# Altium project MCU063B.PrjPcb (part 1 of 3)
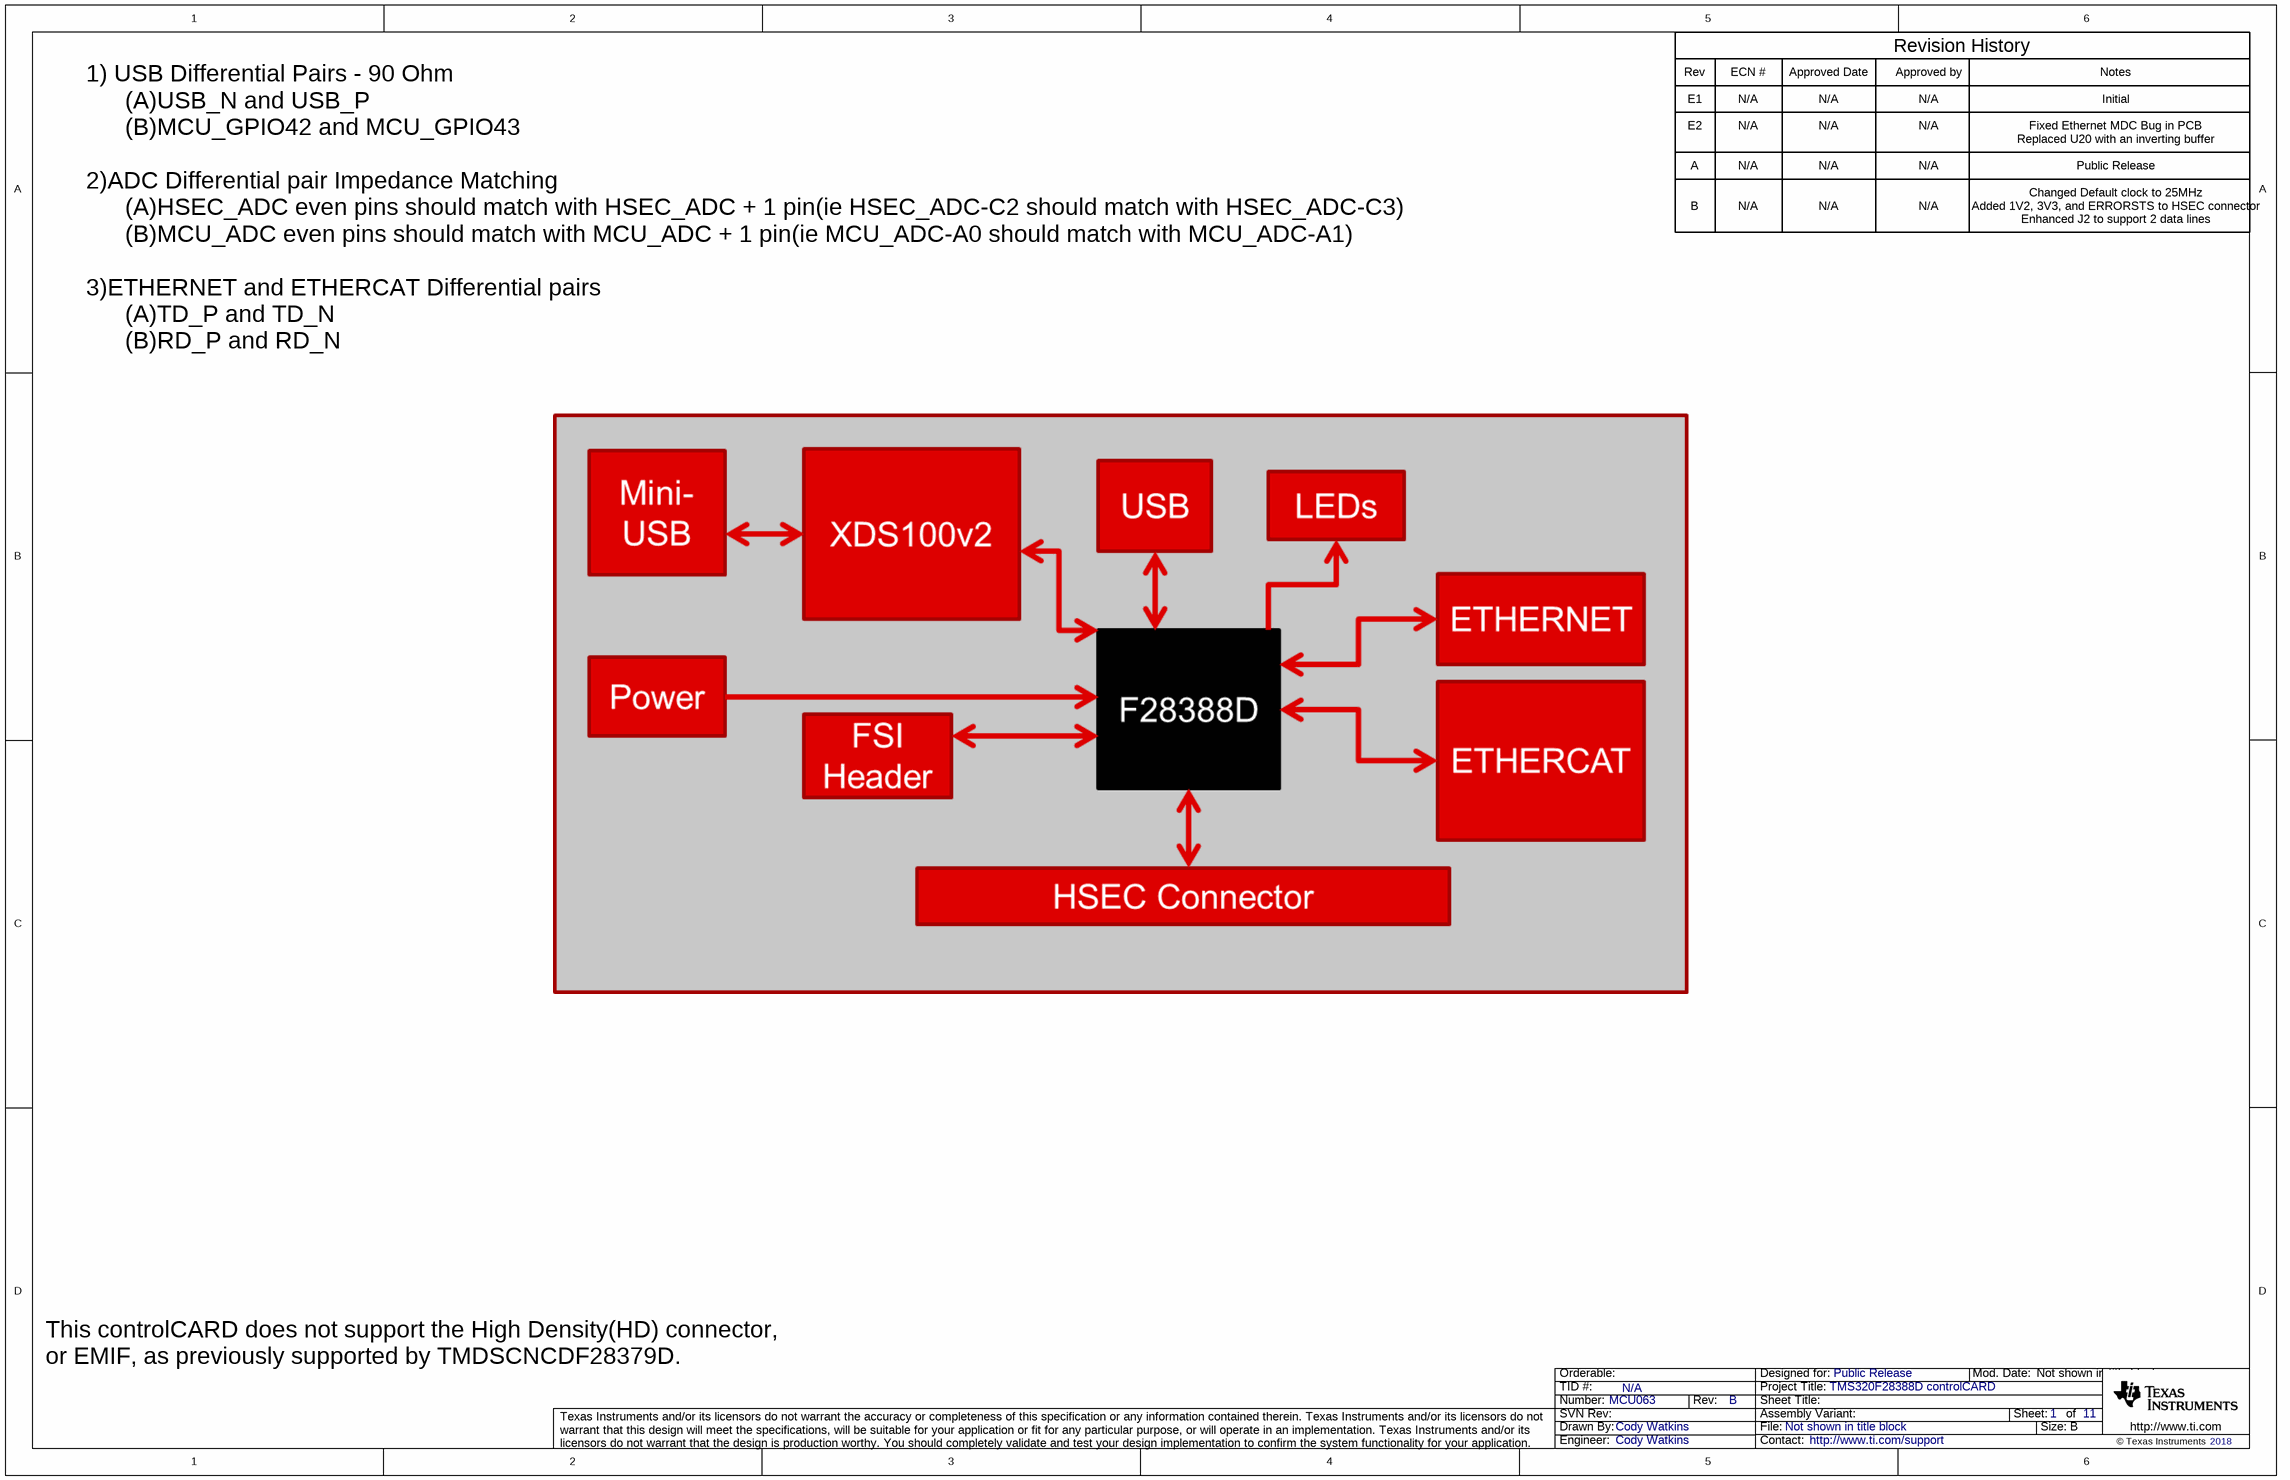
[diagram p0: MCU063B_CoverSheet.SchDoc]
CopyrightYear: 2018; PCB_Layout: QCG; PCB_Rev: B; PRJ_Customer: Public Release; PRJ_Engineer: Cody Watkins; PRJ_Number: MCU063; PRJ_Title: TMS320F28388D controlCARD; SCH_Rev: B; TechSupport: http://www.ti.com/support; TID: N/A
11 sheets, 441 parts. Net scope: global (net labels, ports and power ports of the same name join across sheets).
Board file: MCU063B_PCB.PcbDoc
Sheets:
  MCU063B_CoverSheet.SchDoc
  MCU063B_GPIO.SchDoc
  MCU063B_Support.SchDoc
  MCU063B_ADC.SchDoc
  MCU063B_Power.SchDoc
  MCU063B_USB.SchDoc
  MCU063B_EtherNET.SchDoc
  MCU063B_EtherCAT.SchDoc
  MCU063B_Emulator.SchDoc
  MCU063B_Emulator_interface.SchDoc
  MCU063B_EVM_Hardware.SchDoc

## Sheet MCU063B_CoverSheet.SchDoc
size 431 x 279 mm; Date: Not shown in title block; ApprovedBy: Not shown in title block; CheckedBy: Not shown in title block; Author: Not shown in title block; CompanyName: Not shown in title block; DrawnBy: Cody Watkins; Engineer: Not shown in title block; Organization: Not shown in title block; Address1: Not shown in title block; Address2: Not shown in title block; Address3: Not shown in title block; Address4: Not shown in title block; DocumentNumber: 1; Revision: Use project parameter SCH_Rev; SheetNumber: 1; SheetTotal: 11; PageSetup: Record=PageOptions¦CenterHorizontal=True¦CenterVertical=True¦PrintScale=1.00¦XCorrection=1.00¦YCorrection=1.00¦PrintKind=0¦BorderSize=5000000¦LeftOffset=0¦BottomOffset=0¦Orientation=2¦PaperLength=1000¦PaperWidth=1000¦Scale=100¦PaperSource=15¦PrintQuality=600¦MediaType=1¦DitherType=10¦PaperKind=Letter¦PrintScaleMode=1

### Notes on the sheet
- Rev
- E1
- ECN #
- N/A
- Approved Date
- Approved by
- Revision History
- Notes
- Initial
- E2
- A
- Public Release
- Fixed Ethernet MDC Bug in PCB
- Replaced U20 with an inverting buffer
- B
- Changed Default clock to 25MHz
- Added 1V2, 3V3, and ERRORSTS to HSEC connector
- Enhanced J2 to support 2 data lines
- 1) USB Differential Pairs - 90 Ohm
  (A)USB_N and USB_P
  (B)MCU_GPIO42 and MCU_GPIO43
  2)ADC Differential pair Impedance Matching
  (A)HSEC_ADC even pins should match with HSEC_ADC + 1 pin(ie HSEC_ADC-C2 should match with HSEC_ADC-C3)
  (B)MCU_ADC even pins should match with MCU_ADC + 1 pin(ie MCU_ADC-A0 should match with MCU_ADC-A1)
  3)ETHERNET and ETHERCAT Differential pairs
  (A)TD_P and TD_N
  (B)RD_P and RD_N
- This controlCARD does not support the High Density(HD) connector, or EMIF, as previously supported by TMDSCNCDF28379D.

## Sheet MCU063B_GPIO.SchDoc
size 431 x 279 mm; Date: Not shown in title block; ApprovedBy: Not shown in title block; CheckedBy: Not shown in title block; Author: Not shown in title block; CompanyName: Not shown in title block; DrawnBy: Cody Watkins; Engineer: Not shown in title block; Organization: Not shown in title block; Address1: Not shown in title block; Address2: Not shown in title block; Address3: Not shown in title block; Address4: Not shown in title block; DocumentNumber: 2; Revision: Use project parameter SCH_Rev; SheetNumber: 2; SheetTotal: 11; PageSetup: Record=PageOptions¦CenterHorizontal=True¦CenterVertical=True¦PrintScale=1.00¦XCorrection=1.00¦YCorrection=1.00¦PrintKind=0¦BorderSize=5000000¦LeftOffset=0¦BottomOffset=0¦Orientation=2¦PaperLength=1000¦PaperWidth=1000¦Scale=100¦PaperSource=15¦PrintQuality=600¦MediaType=1¦DitherType=10¦PaperKind=Letter¦PrintScaleMode=1
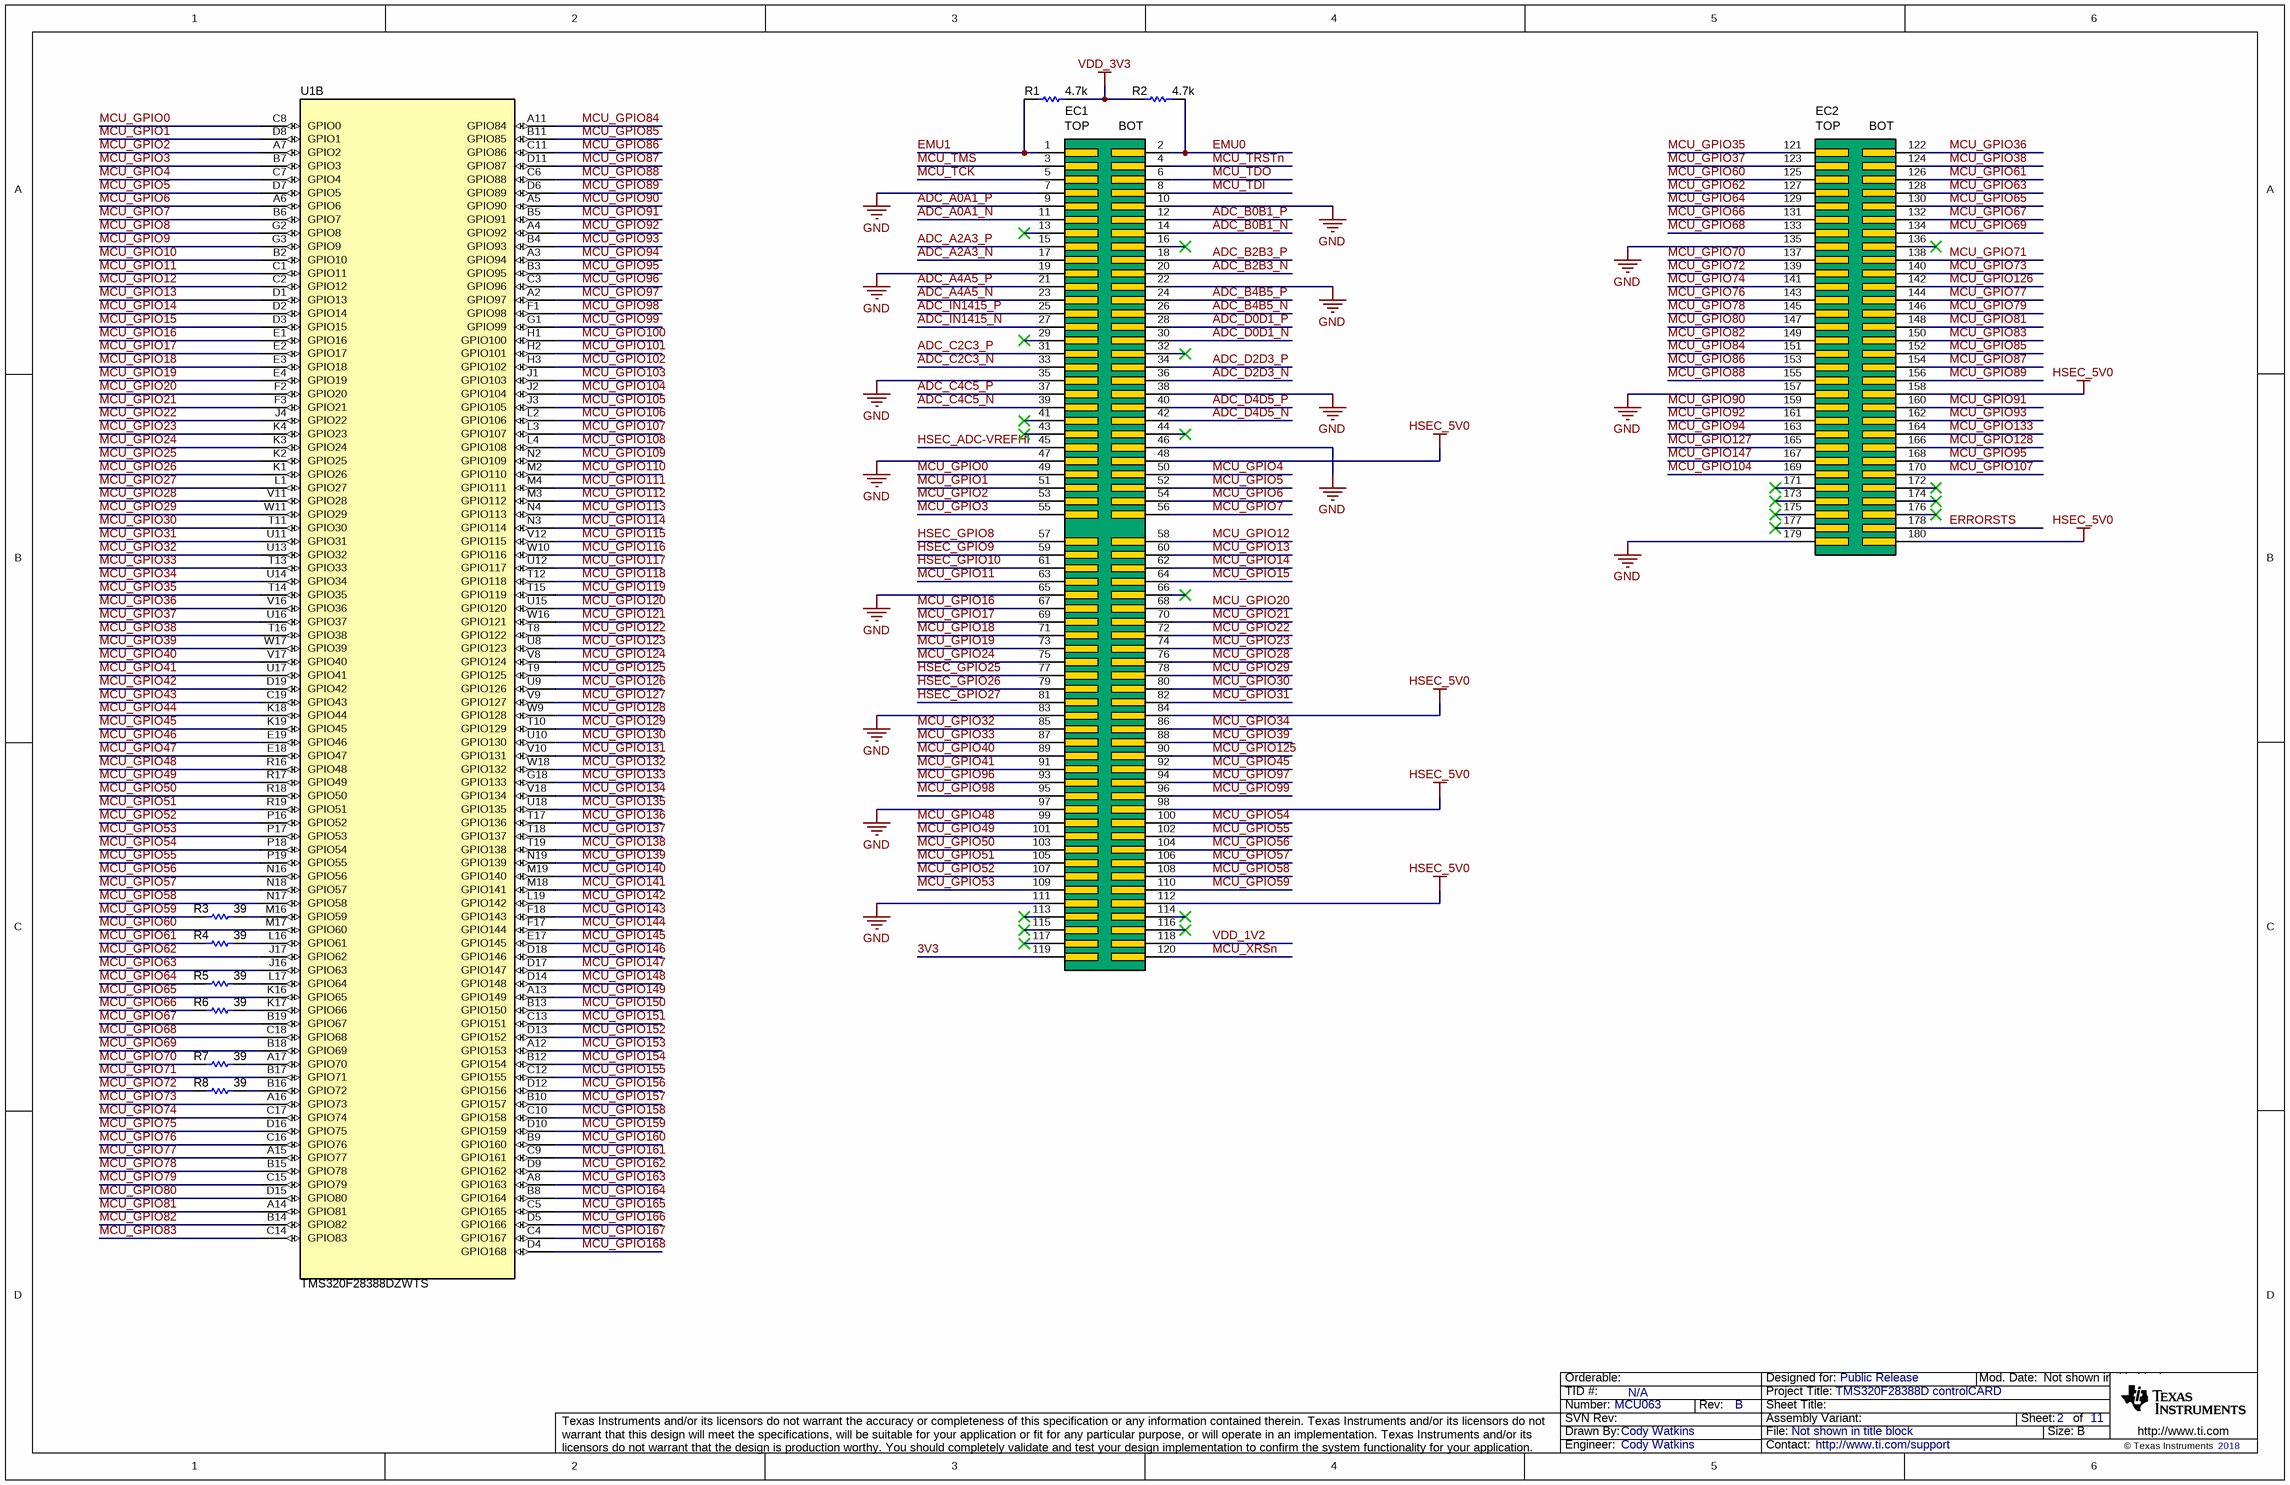
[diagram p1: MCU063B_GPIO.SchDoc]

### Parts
EC1  controlCARD-120HSEC_Edge  [controlCARD-120HSEC_Edge]  (value not drawn)  (no BOM)
EC2  controlCARD-180HSEC-60pinAddon_Edge  [controlCARD-180HSEC-60pinAddon_Edge]  (value not drawn)  (no BOM)
R1  ValueDisplayed: 4.7k  [0402]  (hidden comment: CRCW04024K70JNED)
R2  ValueDisplayed: 4.7k  [0402]  (hidden comment: CRCW04024K70JNED)
R3  ValueDisplayed: 39  [0402]  (hidden comment: CRCW040239R0JNED)
R4  ValueDisplayed: 39  [0402]  (hidden comment: CRCW040239R0JNED)
R5  ValueDisplayed: 39  [0402]  (hidden comment: CRCW040239R0JNED)
R6  ValueDisplayed: 39  [0402]  (hidden comment: CRCW040239R0JNED)
R7  ValueDisplayed: 39  [0402]  (hidden comment: CRCW040239R0JNED)
R8  ValueDisplayed: 39  [0402]  (hidden comment: CRCW040239R0JNED)
U1  TMS320F28388DZWTS  [ZWT0337A]  (part B of 5)

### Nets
3V3: EC1.119
GND: EC1.7 EC1.10 EC1.19 EC1.22 EC1.35 EC1.38 EC1.46 EC1.47 EC1.65 EC1.83 EC1.97 EC1.111 EC2.135 EC2.157 EC2.179
HSEC_5V0: EC1.48 EC1.84 EC1.98 EC1.112 EC2.158 EC2.180
VDD_1V2: EC1.118
VDD_3V3: R1.2 R2.1
ADC_A0A1_N: EC1.11
ADC_A0A1_P: EC1.9
ADC_A2A3_N: EC1.17
ADC_A2A3_P: EC1.15
ADC_A4A5_N: EC1.23
ADC_A4A5_P: EC1.21
ADC_B0B1_N: EC1.14
ADC_B0B1_P: EC1.12
ADC_B2B3_N: EC1.20
ADC_B2B3_P: EC1.18
ADC_B4B5_N: EC1.26
ADC_B4B5_P: EC1.24
ADC_C2C3_N: EC1.33
ADC_C2C3_P: EC1.31
ADC_C4C5_N: EC1.39
ADC_C4C5_P: EC1.37
ADC_D0D1_N: EC1.30
ADC_D0D1_P: EC1.28
ADC_D2D3_N: EC1.36
ADC_D2D3_P: EC1.34
ADC_D4D5_N: EC1.42
ADC_D4D5_P: EC1.40
ADC_IN1415_N: EC1.27
ADC_IN1415_P: EC1.25
EMU0: EC1.2 R2.2
EMU1: EC1.1 R1.1
ERRORSTS: EC2.178
HSEC_ADC-VREFHI: EC1.45
HSEC_GPIO8: EC1.57
HSEC_GPIO9: EC1.59
HSEC_GPIO10: EC1.61
HSEC_GPIO25: EC1.77
HSEC_GPIO26: EC1.79
HSEC_GPIO27: EC1.81
MCU_GPIO0: EC1.49 U1.C8(GPIO0)
MCU_GPIO1: EC1.51 U1.D8(GPIO1)
MCU_GPIO2: EC1.53 U1.A7(GPIO2)
MCU_GPIO3: EC1.55 U1.B7(GPIO3)
MCU_GPIO4: EC1.50 U1.C7(GPIO4)
MCU_GPIO5: EC1.52 U1.D7(GPIO5)
MCU_GPIO6: EC1.54 U1.A6(GPIO6)
MCU_GPIO7: EC1.56 U1.B6(GPIO7)
MCU_GPIO8: U1.G2(GPIO8)
MCU_GPIO9: U1.G3(GPIO9)
MCU_GPIO10: U1.B2(GPIO10)
MCU_GPIO11: EC1.63 U1.C1(GPIO11)
MCU_GPIO12: EC1.58 U1.C2(GPIO12)
MCU_GPIO13: EC1.60 U1.D1(GPIO13)
MCU_GPIO14: EC1.62 U1.D2(GPIO14)
MCU_GPIO15: EC1.64 U1.D3(GPIO15)
MCU_GPIO16: EC1.67 U1.E1(GPIO16)
MCU_GPIO17: EC1.69 U1.E2(GPIO17)
MCU_GPIO18: EC1.71 U1.E3(GPIO18)
MCU_GPIO19: EC1.73 U1.E4(GPIO19)
MCU_GPIO20: EC1.68 U1.F2(GPIO20)
MCU_GPIO21: EC1.70 U1.F3(GPIO21)
MCU_GPIO22: EC1.72 U1.J4(GPIO22)
MCU_GPIO23: EC1.74 U1.K4(GPIO23)
MCU_GPIO24: EC1.75 U1.K3(GPIO24)
MCU_GPIO25: U1.K2(GPIO25)
MCU_GPIO26: U1.K1(GPIO26)
MCU_GPIO27: U1.L1(GPIO27)
MCU_GPIO28: EC1.76 U1.V11(GPIO28)
MCU_GPIO29: EC1.78 U1.W11(GPIO29)
MCU_GPIO30: EC1.80 U1.T11(GPIO30)
MCU_GPIO31: EC1.82 U1.U11(GPIO31)
MCU_GPIO32: EC1.85 U1.U13(GPIO32)
MCU_GPIO33: EC1.87 U1.T13(GPIO33)
MCU_GPIO34: EC1.86 U1.U14(GPIO34)
MCU_GPIO35: EC2.121 U1.T14(GPIO35)
MCU_GPIO36: EC2.122 U1.V16(GPIO36)
MCU_GPIO37: EC2.123 U1.U16(GPIO37)
MCU_GPIO38: EC2.124 U1.T16(GPIO38)
MCU_GPIO39: EC1.88 U1.W17(GPIO39)
MCU_GPIO40: EC1.89 U1.V17(GPIO40)
MCU_GPIO41: EC1.91 U1.U17(GPIO41)
MCU_GPIO42: U1.D19(GPIO42)
MCU_GPIO43: U1.C19(GPIO43)
MCU_GPIO44: U1.K18(GPIO44)
MCU_GPIO45: EC1.92 U1.K19(GPIO45)
MCU_GPIO46: U1.E19(GPIO46)
MCU_GPIO47: U1.E18(GPIO47)
MCU_GPIO48: EC1.99 U1.R16(GPIO48)
MCU_GPIO49: EC1.101 U1.R17(GPIO49)
MCU_GPIO50: EC1.103 U1.R18(GPIO50)
MCU_GPIO51: EC1.105 U1.R19(GPIO51)
MCU_GPIO52: EC1.107 U1.P16(GPIO52)
MCU_GPIO53: EC1.109 U1.P17(GPIO53)
MCU_GPIO54: EC1.100 U1.P18(GPIO54)
MCU_GPIO55: EC1.102 U1.P19(GPIO55)
MCU_GPIO56: EC1.104 U1.N16(GPIO56)
MCU_GPIO57: EC1.106 U1.N18(GPIO57)
MCU_GPIO58: EC1.108 U1.N17(GPIO58)
MCU_GPIO59: EC1.110 R3.1
MCU_GPIO60: EC2.125 U1.M17(GPIO60)
MCU_GPIO61: EC2.126 R4.1
MCU_GPIO62: EC2.127 U1.J17(GPIO62)
MCU_GPIO63: EC2.128 U1.J16(GPIO63)
MCU_GPIO64: EC2.129 R5.1
MCU_GPIO65: EC2.130 U1.K16(GPIO65)
MCU_GPIO66: EC2.131 R6.1
MCU_GPIO67: EC2.132 U1.B19(GPIO67)
MCU_GPIO68: EC2.133 U1.C18(GPIO68)
MCU_GPIO69: EC2.134 U1.B18(GPIO69)
MCU_GPIO70: EC2.137 R7.1
MCU_GPIO71: EC2.138 U1.B17(GPIO71)
MCU_GPIO72: EC2.139 R8.1
MCU_GPIO73: EC2.140 U1.A16(GPIO73)
MCU_GPIO74: EC2.141 U1.C17(GPIO74)
MCU_GPIO75: U1.D16(GPIO75)
MCU_GPIO76: EC2.143 U1.C16(GPIO76)
MCU_GPIO77: EC2.144 U1.A15(GPIO77)
MCU_GPIO78: EC2.145 U1.B15(GPIO78)
MCU_GPIO79: EC2.146 U1.C15(GPIO79)
MCU_GPIO80: EC2.147 U1.D15(GPIO80)
MCU_GPIO81: EC2.148 U1.A14(GPIO81)
MCU_GPIO82: EC2.149 U1.B14(GPIO82)
MCU_GPIO83: EC2.150 U1.C14(GPIO83)
MCU_GPIO84: EC2.151 U1.A11(GPIO84)
MCU_GPIO85: EC2.152 U1.B11(GPIO85)
MCU_GPIO86: EC2.153 U1.C11(GPIO86)
MCU_GPIO87: EC2.154 U1.D11(GPIO87)
MCU_GPIO88: EC2.155 U1.C6(GPIO88)
MCU_GPIO89: EC2.156 U1.D6(GPIO89)
MCU_GPIO90: EC2.159 U1.A5(GPIO90)
MCU_GPIO91: EC2.160 U1.B5(GPIO91)
MCU_GPIO92: EC2.161 U1.A4(GPIO92)
MCU_GPIO93: EC2.162 U1.B4(GPIO93)
MCU_GPIO94: EC2.163 U1.A3(GPIO94)
MCU_GPIO95: EC2.168 U1.B3(GPIO95)
MCU_GPIO96: EC1.93 U1.C3(GPIO96)
MCU_GPIO97: EC1.94 U1.A2(GPIO97)
MCU_GPIO98: EC1.95 U1.F1(GPIO98)
MCU_GPIO99: EC1.96 U1.G1(GPIO99)
MCU_GPIO100: U1.H1(GPIO100)
MCU_GPIO101: U1.H2(GPIO101)
MCU_GPIO102: U1.H3(GPIO102)
MCU_GPIO103: U1.J1(GPIO103)
MCU_GPIO104: EC2.169 U1.J2(GPIO104)
MCU_GPIO105: U1.J3(GPIO105)
MCU_GPIO106: U1.L2(GPIO106)
MCU_GPIO107: EC2.170 U1.L3(GPIO107)
MCU_GPIO108: U1.L4(GPIO108)
MCU_GPIO109: U1.N2(GPIO109)
MCU_GPIO110: U1.M2(GPIO110)
MCU_GPIO111: U1.M4(GPIO111)
MCU_GPIO112: U1.M3(GPIO112)
MCU_GPIO113: U1.N4(GPIO113)
MCU_GPIO114: U1.N3(GPIO114)
MCU_GPIO115: U1.V12(GPIO115)
MCU_GPIO116: U1.W10(GPIO116)
MCU_GPIO117: U1.U12(GPIO117)
MCU_GPIO118: U1.T12(GPIO118)
MCU_GPIO119: U1.T15(GPIO119)
MCU_GPIO120: U1.U15(GPIO120)
MCU_GPIO121: U1.W16(GPIO121)
MCU_GPIO122: U1.T8(GPIO122)
MCU_GPIO123: U1.U8(GPIO123)
MCU_GPIO124: U1.V8(GPIO124)
MCU_GPIO125: EC1.90 U1.T9(GPIO125)
MCU_GPIO126: EC2.142 U1.U9(GPIO126)
MCU_GPIO127: EC2.165 U1.V9(GPIO127)
MCU_GPIO128: EC2.166 U1.W9(GPIO128)
MCU_GPIO129: U1.T10(GPIO129)
MCU_GPIO130: U1.U10(GPIO130)
MCU_GPIO131: U1.V10(GPIO131)
MCU_GPIO132: U1.W18(GPIO132)
MCU_GPIO133: EC2.164 U1.G18(GPIO133)
MCU_GPIO134: U1.V18(GPIO134)
MCU_GPIO135: U1.U18(GPIO135)
MCU_GPIO136: U1.T17(GPIO136)
MCU_GPIO137: U1.T18(GPIO137)
MCU_GPIO138: U1.T19(GPIO138)
MCU_GPIO139: U1.N19(GPIO139)
MCU_GPIO140: U1.M19(GPIO140)
MCU_GPIO141: U1.M18(GPIO141)
MCU_GPIO142: U1.L19(GPIO142)
MCU_GPIO143: U1.F18(GPIO143)
MCU_GPIO144: U1.F17(GPIO144)
MCU_GPIO145: U1.E17(GPIO145)
MCU_GPIO146: U1.D18(GPIO146)
MCU_GPIO147: EC2.167 U1.D17(GPIO147)
MCU_GPIO148: U1.D14(GPIO148)
MCU_GPIO149: U1.A13(GPIO149)
MCU_GPIO150: U1.B13(GPIO150)
MCU_GPIO151: U1.C13(GPIO151)
MCU_GPIO152: U1.D13(GPIO152)
MCU_GPIO153: U1.A12(GPIO153)
MCU_GPIO154: U1.B12(GPIO154)
MCU_GPIO155: U1.C12(GPIO155)
MCU_GPIO156: U1.D12(GPIO156)
MCU_GPIO157: U1.B10(GPIO157)
MCU_GPIO158: U1.C10(GPIO158)
MCU_GPIO159: U1.D10(GPIO159)
MCU_GPIO160: U1.B9(GPIO160)
MCU_GPIO161: U1.C9(GPIO161)
MCU_GPIO162: U1.D9(GPIO162)
MCU_GPIO163: U1.A8(GPIO163)
MCU_GPIO164: U1.B8(GPIO164)
MCU_GPIO165: U1.C5(GPIO165)
MCU_GPIO166: U1.D5(GPIO166)
MCU_GPIO167: U1.C4(GPIO167)
MCU_GPIO168: U1.D4(GPIO168)
MCU_TCK: EC1.5
MCU_TDI: EC1.8
MCU_TDO: EC1.6
MCU_TMS: EC1.3
MCU_TRSTn: EC1.4
MCU_XRSn: EC1.120
NetR3_2: R3.2 U1.M16(GPIO59)
NetR4_2: R4.2 U1.L16(GPIO61)
NetR5_2: R5.2 U1.L17(GPIO64)
NetR6_2: R6.2 U1.K17(GPIO66)
NetR7_2: R7.2 U1.A17(GPIO70)
NetR8_2: R8.2 U1.B16(GPIO72)

Not connected (* = marked no-connect by the designer): EC1 13* 16* 29* 32* 41* 43* 44* 66* 113* 114* 115* 116* 117*; EC2 136* 171* 172* 173* 174* 175* 176* 177*

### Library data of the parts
EC1 = CMP-0003813-2: C2000 controlCARD-120HSEC Edge Connector for Samtec HSEC8-160-01-L-DV-A-BL; Manufacturer: Any; Note: The pin numbering does not match Samtec datasheet
EC2 = CMP-0081961-1: C2000 controlCARD-180HSEC (60-pin addon) Edge connector for Samtec HSEC8-130-01-L-DV-A; Manufacturer: Any; Note: The pin numbering does not match Samtec datasheet
R1 R2 = CMP-0026938-5: RES, 4.7 k, 5%, 0.063 W, AEC-Q200 Grade 0, 0402; Manufacturer: Vishay-Dale; Power_W: 63mW; TempCo: 200 ppm/C; Value_Code: 4k70; Value: 4.7k; EIA_Code: E24; SizeX_mm: 1; SizeY_mm: 0.5; SizeZ_mm: 0.6; Value2: 0.063W; AEC Qualified: Y; VDC_V: 50V; AEC Category: Q200; AEC Grade: 0
R3-R8 = CMP-0026916-3: RES, 39, 5%, 0.063 W, AEC-Q200 Grade 0, 0402; Manufacturer: Vishay-Dale; Power_W: 63mW; TempCo: 200 ppm/C; Value_Code: 39R0; Value: 39; EIA_Code: E24; SizeX_mm: 1; SizeY_mm: 0.5; SizeZ_mm: 0.6; Value2: 0.063W; AEC Qualified: Y; VDC_V: 50V; AEC Category: Q200; AEC Grade: 0
U1 = CMP-0081777-3: TMS320F28388DZWTS, ZWT0337A (NFBGA-337); Manufacturer: Texas Instruments; SizeAreaWB_mm2: 324; SizeArea_mm2: 256; AEC Qualified: N; AEC Category: Q200; SizeZ_mm: 1.4; SizeY_mm: 16; CompType: IC

## Sheet MCU063B_Support.SchDoc
size 431 x 279 mm; Date: Not shown in title block; ApprovedBy: Not shown in title block; CheckedBy: Not shown in title block; Author: Not shown in title block; CompanyName: Not shown in title block; DrawnBy: Cody Watkins; Engineer: Not shown in title block; Organization: Not shown in title block; Address1: Not shown in title block; Address2: Not shown in title block; Address3: Not shown in title block; Address4: Not shown in title block; DocumentNumber: 3; Revision: Use project parameter SCH_Rev; SheetNumber: 3; SheetTotal: 11; PageSetup: Record=PageOptions¦CenterHorizontal=True¦CenterVertical=True¦PrintScale=1.00¦XCorrection=1.00¦YCorrection=1.00¦PrintKind=0¦BorderSize=5000000¦LeftOffset=0¦BottomOffset=0¦Orientation=2¦PaperLength=1000¦PaperWidth=1000¦Scale=100¦PaperSource=15¦PrintQuality=600¦MediaType=1¦DitherType=10¦PaperKind=Letter¦PrintScaleMode=1
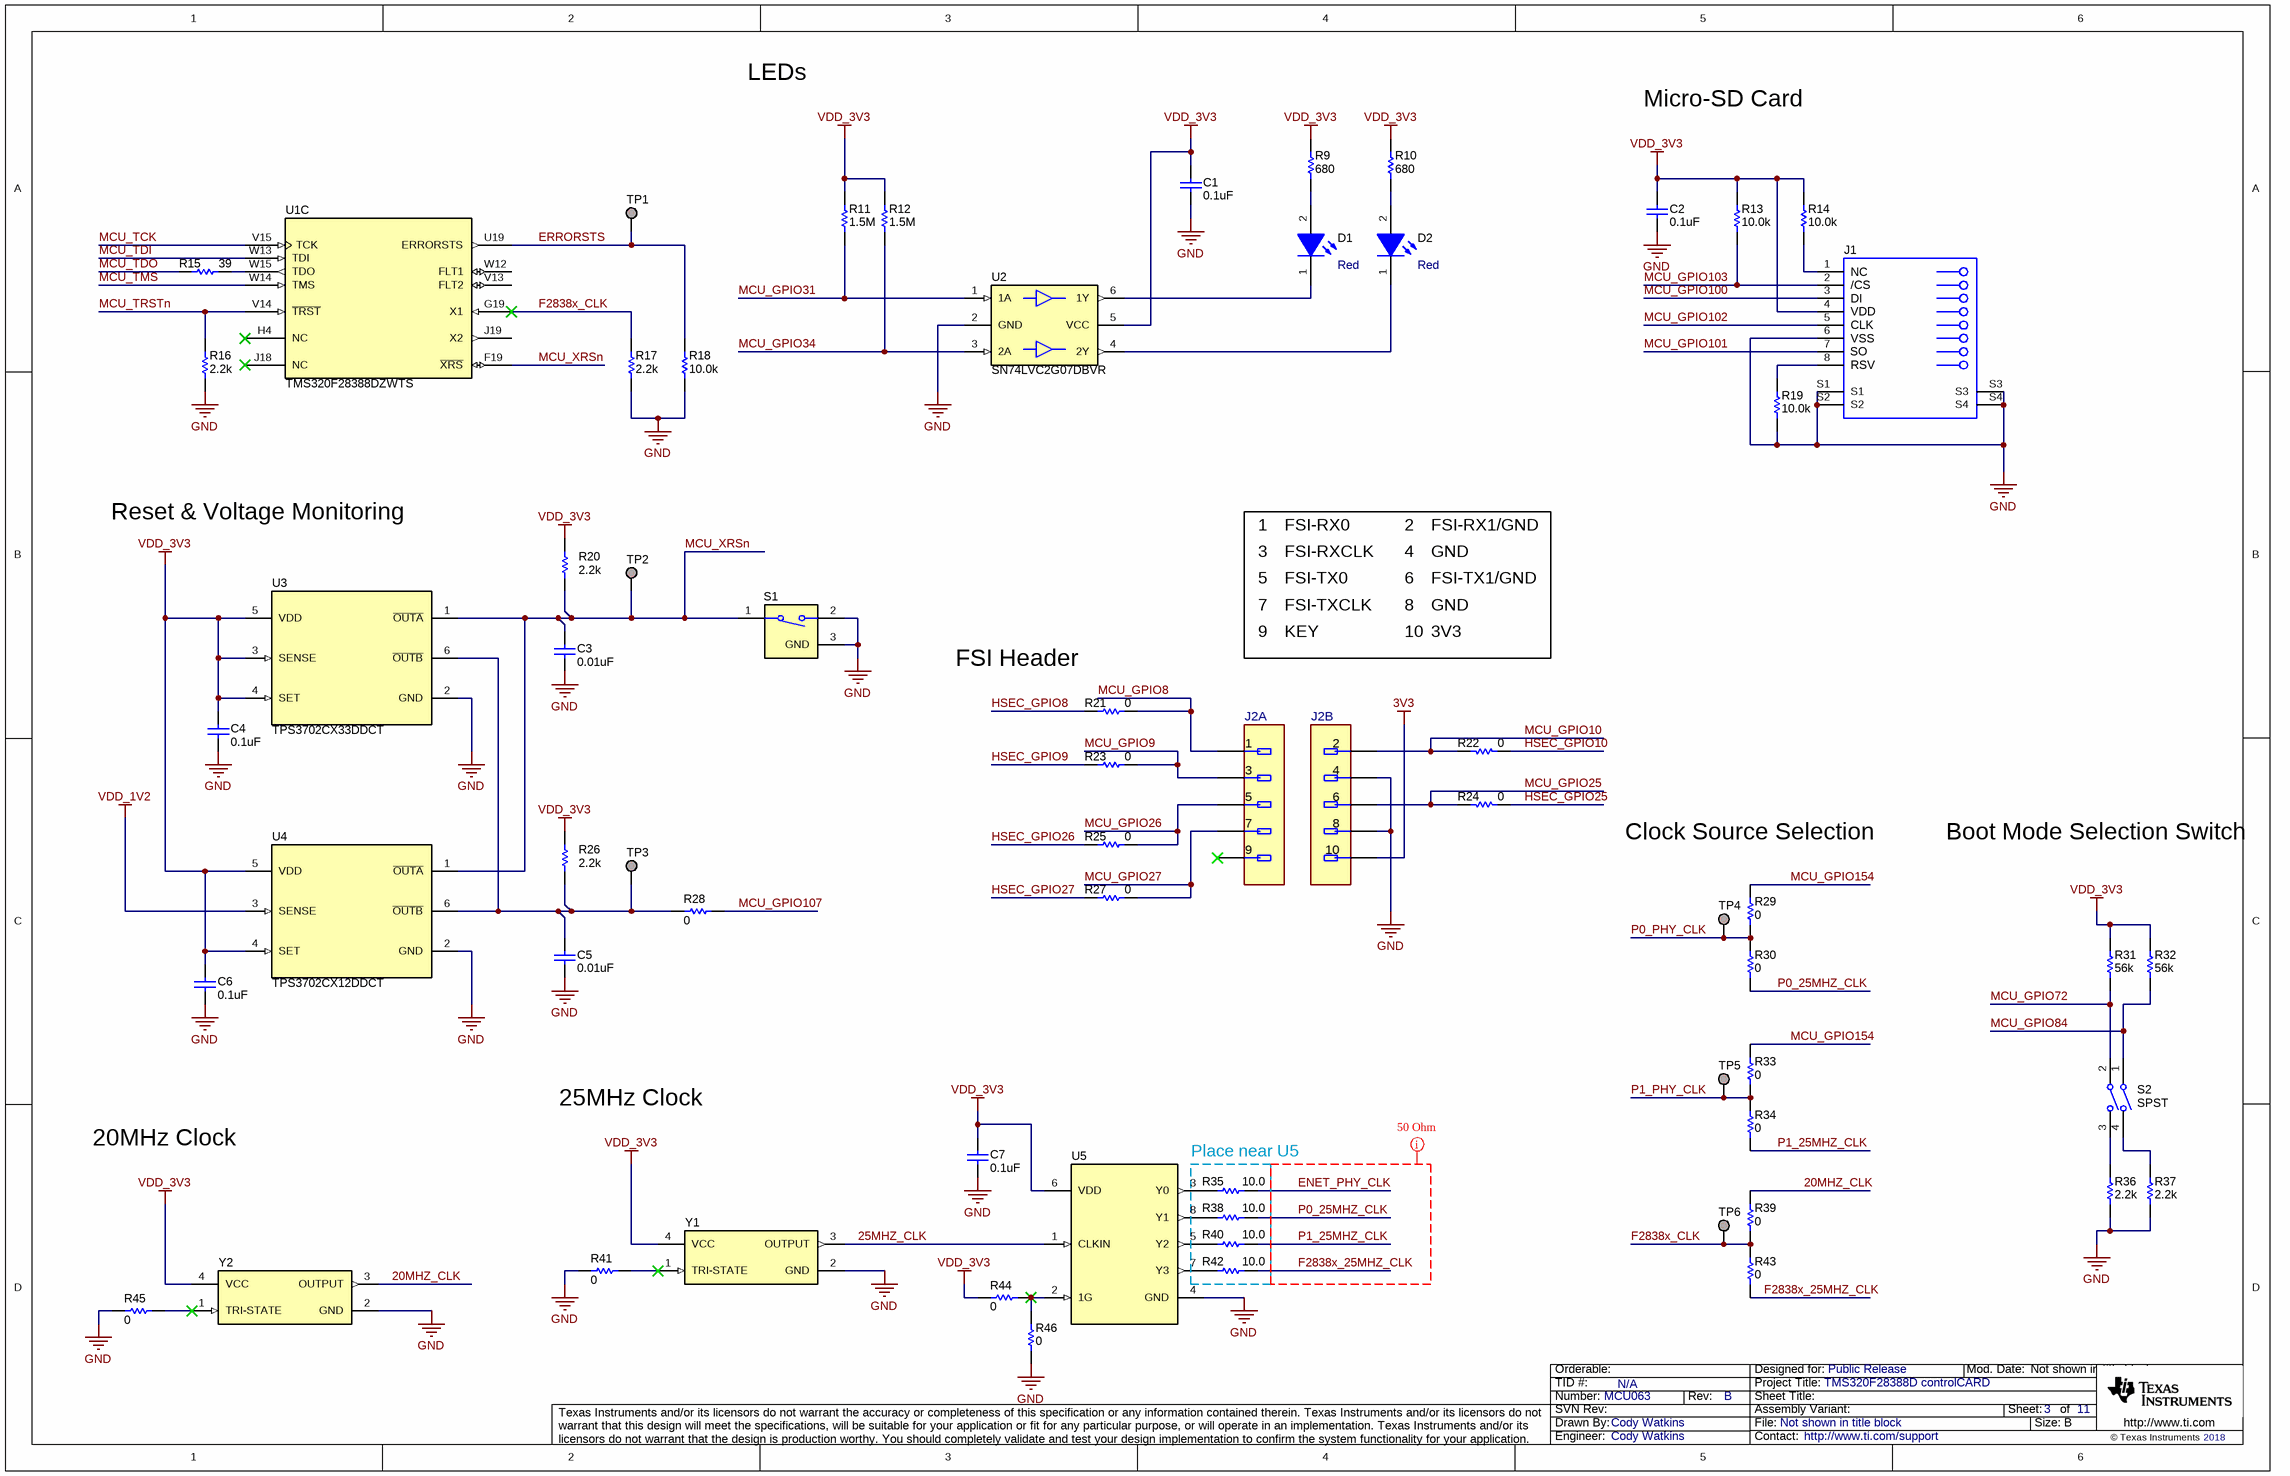
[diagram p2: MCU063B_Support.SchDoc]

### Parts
C1  ValueDisplayed: 0.1uF  [0402]  (hidden comment: CL05B104KP5NNNC)
C2  ValueDisplayed: 0.1uF  [0402]  (hidden comment: CL05B104KP5NNNC)
C3  ValueDisplayed: 0.01uF  [0402]  (hidden comment: C0402C103J5RACTU)
C4  ValueDisplayed: 0.1uF  [0402]  (hidden comment: CL05B104KP5NNNC)
C5  ValueDisplayed: 0.01uF  [0402]  (hidden comment: C0402C103J5RACTU)
C6  ValueDisplayed: 0.1uF  [0402]  (hidden comment: CL05B104KP5NNNC)
C7  ValueDisplayed: 0.1uF  [0402]  (hidden comment: CL05B104KP5NNNC)
D1  value Red  [WL-SMCW_RED_0805]  (hidden comment: 150080SS75000)
D2  value Red  [WL-SMCW_RED_0805]  (hidden comment: 150080SS75000)
J1  2908-05WB-MG  [3M_2908-05WB-MG]  (value not drawn)
J2  TMM-105-01-T-D  [FP-TMM-105-01-T-D_HDR10-MFG]  (value not drawn)  (parts A,B of 2)
R9  ValueDisplayed: 680  [0402]  (hidden comment: CRCW0402680RJNED)
R10  ValueDisplayed: 680  [0402]  (hidden comment: CRCW0402680RJNED)
R11  ValueDisplayed: 1.5M  [0402]  (hidden comment: CRCW04021M50JNED)
R12  ValueDisplayed: 1.5M  [0402]  (hidden comment: CRCW04021M50JNED)
R13  ValueDisplayed: 10.0k  [0402]  (hidden comment: RC0402FR-0710KL)
R14  ValueDisplayed: 10.0k  [0402]  (hidden comment: RC0402FR-0710KL)
R15  ValueDisplayed: 39  [0402]  (hidden comment: CRCW040239R0JNED)
R16  ValueDisplayed: 2.2k  [0402]  (hidden comment: CRCW04022K20JNED)
R17  ValueDisplayed: 2.2k  [0402]  (hidden comment: CRCW04022K20JNED)
R18  ValueDisplayed: 10.0k  [0402]  (hidden comment: RC0402FR-0710KL)
R19  ValueDisplayed: 10.0k  [0402]  (hidden comment: RC0402FR-0710KL)
R20  ValueDisplayed: 2.2k  [0402]  (hidden comment: CRCW04022K20JNED)
R21  ValueDisplayed: 0  [0603]  (hidden comment: CRCW06030000Z0EA)
R22  ValueDisplayed: 0  [0603]  (hidden comment: CRCW06030000Z0EA)
R23  ValueDisplayed: 0  [0603]  (hidden comment: CRCW06030000Z0EA)
R24  ValueDisplayed: 0  [0603]  (hidden comment: CRCW06030000Z0EA)
R25  ValueDisplayed: 0  [0603]  (hidden comment: CRCW06030000Z0EA)
R26  ValueDisplayed: 2.2k  [0402]  (hidden comment: CRCW04022K20JNED)
R27  ValueDisplayed: 0  [0603]  (hidden comment: CRCW06030000Z0EA)
R28  ValueDisplayed: 0  [0603]  (hidden comment: CRCW06030000Z0EA)
R29  ValueDisplayed: 0  [0603]  (hidden comment: CRCW06030000Z0EA)
R30  ValueDisplayed: 0  [0603]  (hidden comment: CRCW06030000Z0EA)
R31  ValueDisplayed: 56k  [0402]  (hidden comment: CRCW040256K0JNED)
R32  ValueDisplayed: 56k  [0402]  (hidden comment: CRCW040256K0JNED)
R33  ValueDisplayed: 0  [0603]  (hidden comment: CRCW06030000Z0EA)
R34  ValueDisplayed: 0  [0603]  (hidden comment: CRCW06030000Z0EA)
R35  ValueDisplayed: 10.0  [CPF0402]  (hidden comment: CPF0402B10RE1)
R36  ValueDisplayed: 2.2k  [0402]  (hidden comment: CRCW04022K20JNED)
R37  ValueDisplayed: 2.2k  [0402]  (hidden comment: CRCW04022K20JNED)
R38  ValueDisplayed: 10.0  [CPF0402]  (hidden comment: CPF0402B10RE1)
R39  ValueDisplayed: 0  [0603]  (hidden comment: CRCW06030000Z0EA)
R40  ValueDisplayed: 10.0  [CPF0402]  (hidden comment: CPF0402B10RE1)
R41  ValueDisplayed: 0  [0402]  (hidden comment: CRCW04020000Z0EDHP)
R42  ValueDisplayed: 10.0  [CPF0402]  (hidden comment: CPF0402B10RE1)
R43  ValueDisplayed: 0  [0603]  (hidden comment: CRCW06030000Z0EA)
R44  ValueDisplayed: 0  [0402]  (hidden comment: CRCW04020000Z0EDHP)
R45  ValueDisplayed: 0  [0402]  (hidden comment: CRCW04020000Z0EDHP)
R46  ValueDisplayed: 0  [0402]  (hidden comment: CRCW04020000Z0EDHP)
S1  B3U-1100P  [SW_B3U-1100P]  (value not drawn)
S2  Circuit: SPST  [SW_218-2LP]  (hidden comment: 218-2LPST)
TP1  TESTPOINT  [TP_50MIL-25MILHOLE]  (value not drawn)  (no BOM)
TP2  TESTPOINT  [TP_50MIL-25MILHOLE]  (value not drawn)  (no BOM)
TP3  TESTPOINT  [TP_50MIL-25MILHOLE]  (value not drawn)  (no BOM)
TP4  TESTPOINT  [TP_50MIL-25MILHOLE]  (value not drawn)  (no BOM)
TP5  TESTPOINT  [TP_50MIL-25MILHOLE]  (value not drawn)  (no BOM)
TP6  TESTPOINT  [TP_50MIL-25MILHOLE]  (value not drawn)  (no BOM)
U1  TMS320F28388DZWTS  [ZWT0337A]  (part C of 5)
U2  SN74LVC2G07DBVR  [DBV0006A_N]
U3  TPS3702CX33DDCT  [DDC0006A_N]
U4  TPS3702CX12DDCT  [DDC0006A_N]
U5  CDCLVC1104PW  [PW0008A_N]  (value not drawn)
Y1  ECS-2520S33-250-FN-TR  [ECS_ECS-2520S]  (value not drawn)
Y2  ECS-2520S33-200-FN-TR  [ECS_ECS-2520S]  (value not drawn)

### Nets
3V3: J2.10
GND: C1.2 C2.2 C3.2 C4.2 C5.2 C6.2 C7.2 J1.6(VSS) J1.S1 J1.S2 J1.S3 J1.S4 J2.4 J2.8 R16.1 R17.1 R18.1 R19.1 R36.2 R37.1 R41.2 R45.2 R46.2 S1.2 S1.3(GND) U2.2(GND) U3.2(GND) U4.2(GND) U5.4(GND) Y1.2(GND) Y2.2(GND)
VDD_1V2: U4.3(SENSE)
VDD_3V3: C1.1 C2.1 C4.1 C6.1 C7.1 J1.4(VDD) R9.1 R10.1 R11.2 R12.2 R13.2 R14.2 R20.2 R26.2 R31.1 R32.2 R44.1 U2.5(VCC) U3.3(SENSE) U3.4(SET) U3.5(VDD) U4.4(SET) U4.5(VDD) U5.6(VDD) Y1.4(VCC) Y2.4(VCC)
20MHZ_CLK: R39.1 Y2.3(OUTPUT)
25MHZ_CLK: U5.1(CLKIN) Y1.3(OUTPUT)
ENET_PHY_CLK: R35.2
ERRORSTS: R18.2 TP1.1 U1.U19(ERRORSTS)
F2838x_25MHZ_CLK: R42.2 R43.2
F2838x_CLK: R17.2 R39.2 R43.1 TP6.1 U1.G19(X1)
HSEC_GPIO8: R21.2
HSEC_GPIO9: R23.2
HSEC_GPIO10: R22.1
HSEC_GPIO25: R24.1
HSEC_GPIO26: R25.2
HSEC_GPIO27: R27.2
MCU_GPIO8: J2.1 R21.1
MCU_GPIO9: J2.3 R23.1
MCU_GPIO10: J2.2 R22.2
MCU_GPIO25: J2.6 R24.2
MCU_GPIO26: J2.5 R25.1
MCU_GPIO27: J2.7 R27.1
MCU_GPIO31: R11.1 U2.1(1A)
MCU_GPIO34: R12.1 U2.3(2A)
MCU_GPIO72: R31.2 S2.2
MCU_GPIO84: R32.1 S2.1
MCU_GPIO100: J1.3(CMD)
MCU_GPIO101: J1.7(DAT0)
MCU_GPIO102: J1.5(CLK)
MCU_GPIO103: J1.2(CD/DAT3) R13.1
MCU_GPIO107: R28.2
MCU_GPIO154: R29.1 R33.1
MCU_TCK: U1.V15(TCK)
MCU_TDI: U1.W13(TDI)
MCU_TDO: R15.1
MCU_TMS: U1.W14(TMS)
MCU_TRSTn: R16.2 U1.V14(~{TRST})
MCU_XRSn: C3.1 R20.1 S1.1 TP2.1 U1.F19(~{XRS}) U3.1(~{OUTA}) U4.1(~{OUTA})
P0_25MHZ_CLK: R30.2 R38.2
P0_PHY_CLK: R29.2 R30.1 TP4.1
P1_25MHZ_CLK: R34.2 R40.2
P1_PHY_CLK: R33.2 R34.1 TP5.1
NetC5_1: C5.1 R26.1 R28.1 TP3.1 U3.6(~{OUTB}) U4.6(~{OUTB})
NetD1_1: D1.1(K) U2.6(1Y)
NetD1_2: D1.2(A) R9.2
NetD2_1: D2.1(K) U2.4(2Y)
NetD2_2: D2.2(A) R10.2
NetJ1_1: J1.1(DAT2) R14.1
NetJ1_8: J1.8(DAT1) R19.2
NetR15_2: R15.2 U1.W15(TDO)
NetR35_1: R35.1 U5.3(Y0)
NetR36_1: R36.1 S2.3
NetR37_2: R37.2 S2.4
NetR38_1: R38.1 U5.8(Y1)
NetR40_1: R40.1 U5.5(Y2)
NetR41_1: R41.1 Y1.1(TRI-STATE)
NetR42_1: R42.1 U5.7(Y3)
NetR44_2: R44.2 R46.1 U5.2(1G)
NetR45_1: R45.1 Y2.1(TRI-STATE)

Not connected (* = marked no-connect by the designer): J2 9*; U1 H4(NC)* J18(NC)* J19(X2) V13(FLT2) W12(FLT1)

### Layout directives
50 Ohm Impedance: Undefined: ENET_PHY_CLK, F2838x_25MHZ_CLK, P0_25MHZ_CLK, P1_25MHZ_CLK

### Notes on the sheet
- LEDs
- Micro-SD Card
- Reset & Voltage Monitoring
- 1
- 3
- FSI-RX0
- FSI-RXCLK
- 4
- 2
- FSI-RX1/GND
- GND
- 5
- 7
- 9
- FSI-TX0
- FSI-TXCLK
- KEY
- 8
- 10
- 6
- FSI-TX1/GND
- 3V3
- (near R21) FSI Header
- Clock Source Selection
- Boot Mode Selection Switch
- 25MHz Clock
- 20MHz Clock
- Place near U5

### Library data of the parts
C1 C2 C4 C6 C7 = CMP-0006343-2: CAP, CERM, 0.1 uF, 10 V, +/- 10%, X7R, 0402; Manufacturer: Samsung Electro-Mechanics; Polarized: N; Value: 0.1uF; U/M: EA; Cap_F: 100nF; Value1: Unknown; VDC_V: 10V; TaMin_C: -55°C; TaMax_C: 125°C; AEC Category: Q200; SizeArea_mm2: 0.5; SizeAreaWB_mm2: 3; SizeX_mm: 1; SizeZ_mm: 0.6
C3 C5 = CMP-0006236-2: CAP, CERM, 0.01 uF, 50 V, +/- 5%, X7R, 0402; Manufacturer: Kemet; TaMin_C: -55°C; Polarized: N; SizeAreaWB_mm2: 3; Value1: Unknown; U/M: EA; Value: 0.01uF; TaMax_C: 125°C; SizeZ_mm: 0.6; SizeX_mm: 1; SizeY_mm: 0.5; Value2: 50V; Cap_F: 10nF; AEC Category: Q200
D1 = CMP-0002951-3: LED, Red, SMD; Manufacturer: Wurth Elektronik; Type: AlInGaP; Angle: 140; Vr_V: 5V; Ir_A: 25µA; Vf_V: 1.9V; Value1: 0.072W; Tjmax_C: 85°C; Io_A: 30mA; Power_TotalModule: 72mW
D2 = CMP-0002951-3: LED, Red, SMD; Manufacturer: Wurth Elektronik; Type: AlInGaP; Vf_V: 1.9V; Io_A: 30mA; Vr_V: 5V; Ir_A: 25µA; Tjmax_C: 85°C; Power_TotalModule: 72mW; Value1: 0.072W; Angle: 140
J1 = CMP-0075148-2: Connector, Micro SD, R/A, SMD; Manufacturer: 3M; Gender: Female; Row_Count: 1; Pitch_mm: 1.1; ContactFinish: Gold
J2 = CMP-0086568-1: Board-To-Board Connector, TMM Series, 10 Contacts, Header, 2 mm, Through Hole, 2 Rows; Manufacturer: Samtec; ContactFinish: Tin,Nickel; Voltage_V: 281V; Symbol Name: SYM-TMM-105-01-T-D; Row_Count: 2; Current_A: 3.2A
R9 R10 = CMP-0026962-3: RES, 680, 5%, 0.063 W, AEC-Q200 Grade 0, 0402; Manufacturer: Vishay-Dale; Value: 680; Value_Code: 680R; Power_W: 63mW; Value2: 0.063W; VDC_V: 50V; TempCo: 200 ppm/C; EIA_Code: E24; AEC Category: Q200; AEC Qualified: Y; AEC Grade: 0; SizeArea_mm2: 0.5; SizeX_mm: 1; SizeZ_mm: 0.6
R11 R12 = CMP-0026863-2: RES, 1.5 M, 5%, 0.063 W, AEC-Q200 Grade 0, 0402; Manufacturer: Vishay-Dale; Power_W: 63mW; TempCo: 200 ppm/C; Value_Code: 1M50; Value: 1.5Meg; EIA_Code: E24; SizeX_mm: 1; SizeY_mm: 0.5; SizeZ_mm: 0.6; Value2: 0.063W; AEC Qualified: Y; VDC_V: 50V; AEC Category: Q200; AEC Grade: 0
R13 R14 R18 R19 = CMP-0078669-1: RES, 10.0 k, 1%, 0.063 W, 0402; Manufacturer: Yageo America; Power_W: 63mW; Green_Lifecycle: Active; TempCo: 100 ppm/C; Value_Code: 10k0; Green_REACh: Passed; Value: 10.0k; EIA_Code: E96; Res_ohm: 10k; SizeX_mm: 1; SizeY_mm: 0.5; SizeZ_mm: 0.6; Value2: 0.063W; AEC Qualified: N; AEC Category: Q200
R15 = CMP-0026916-3: as R3 on sheet MCU063B_GPIO
R16 R17 = CMP-0026890-5: RES, 2.2 k, 5%, 0.063 W, AEC-Q200 Grade 0, 0402; Manufacturer: Vishay-Dale; Power_W: 63mW; TempCo: 200 ppm/C; Value_Code: 2k20; Value: 2.2k; EIA_Code: E24; SizeX_mm: 1; SizeY_mm: 0.5; SizeZ_mm: 0.6; Value2: 0.063W; AEC Qualified: Y; VDC_V: 50V; AEC Category: Q200; AEC Grade: 0
R20 R26 R36 R37 = CMP-0026890-5: RES, 2.2 k, 5%, 0.063 W, AEC-Q200 Grade 0, 0402; Manufacturer: Vishay-Dale; Value: 2.2k; Value_Code: 2k20; Power_W: 63mW; Value2: 0.063W; VDC_V: 50V; TempCo: 200 ppm/C; EIA_Code: E24; AEC Category: Q200; AEC Qualified: Y; AEC Grade: 0; SizeArea_mm2: 0.5; SizeX_mm: 1; SizeZ_mm: 0.6
R21-R25 R27-R30 R33 R34 R39 R43 = CMP-0025697-4: RES, 0, 5%, 0.1 W, AEC-Q200 Grade 0, 0603; Manufacturer: Vishay-Dale; Value: 0; Value_Code: 0000; Power_W: 100mW; Value2: 0.1W; VDC_V: 75V; TempCo: 200 ppm/C; EIA_Code: E24; AEC Category: Q200; AEC Qualified: Y; SizeArea_mm2: 1.28; SizeX_mm: 1.6; SizeY_mm: 0.8; SizeZ_mm: 1
R31 R32 = CMP-0026949-3: RES, 56 k, 5%, 0.063 W, AEC-Q200 Grade 0, 0402; Manufacturer: Vishay-Dale; Value: 56k; Value_Code: 56k0; Power_W: 63mW; Value2: 0.063W; VDC_V: 50V; TempCo: 200 ppm/C; EIA_Code: E24; AEC Category: Q200; AEC Qualified: Y; AEC Grade: 0; SizeArea_mm2: 0.5; SizeX_mm: 1; SizeZ_mm: 0.6
R35 R38 R40 R42 = CMP-0026765-1: RES, 10.0, 0.1%, 0.063 W, 0402; Manufacturer: TE Connectivity; Power_W: 63mW; TempCo: 25 ppm/C; Value_Code: 10R0; U/M: EA; Value: 10.0; EIA_Code: E192; Res_ohm: 10; SizeX_mm: 1; SizeY_mm: 0.5; SizeZ_mm: 0.35; Value2: 0.063W; AEC Qualified: N; AEC Category: Q200
R41 R44-R46 = CMP-0081856-1: RES, 0, 0%, 0.2 W, AEC-Q200 Grade 0, 0402; Manufacturer: Vishay-Dale; SizeAreaWB_mm2: 3; SizeArea_mm2: 0.5; AEC Qualified: Y; AEC Category: Q200; Value: 0; SizeZ_mm: 0.6; Power_W: 200mW; VDC_V: 50V; Value2: 0.2W; SizeX_mm: 1
S1 = CMP-0002193-2: Switch, SPST-NO, Off-Mom, 12 V, SMD; Manufacturer: Omron Electronic Components; CurrentRating_mA: 50A; PositionCount: 1; VDC_V: 12V
S2 = CMP-0002230-1: Switch, SPST, 2 Pos, 25mA, 24VDC, SMD; Manufacturer: CTS Electrocomponents; VDC_V: 24V; SwitchFunction: Off-On; PositionCount: 2; CurrentRating_mA: 25A
TP1-TP6 = CMP-0078143-3: TEST POINT.  No entry in BOM.
U1 = CMP-0081777-3: as U1 on sheet MCU063B_GPIO
U2 = CMP-0051789-2: Dual Buffer/Driver with Open-Drain Output, DBV0006A, LARGE T&R; Manufacturer: Texas Instruments; 3-State Output: No; Bits(#): 2; F @ Nom Voltage(Max)(Mhz): 150; ICC @ Nom Voltage(Max)(mA): 0.01; Input Type: CMOS/TTL; Logic: True; Output Drive (IOL/IOH)(Max)(mA): 32/-32; Output Type: CMOS; Rating: Catalog; Sub-Family: Inverting Buffer/Driver; Technology Family: LVC; tpd @ Nom Voltage(Max)(ns): 8.6,4.4,3.7,2.9; VCC(Max)(V): 5.5; VCC(Min)(V): 1.65; Voltage(Nom)(V): 1.8,2.5,3.3,5; AEC Category: Q200; AEC Qualified: N; CompType: IC; Green_Lifecycle: Active; Green_REACh: Passed; SizeArea_mm2: 8.12; SizeAreaWB_mm2: 14.82; SizeX_mm: 2.8; SizeY_mm: 2.9; SizeZ_mm: 1.45
U3 = CMP-0080903-1: High-Accuracy, Fixed-Threshold OV/UV Monitor, DDC0006A (SOT-23-T-6); Alternate PartNumber: TPS3702CX33DDCR; Alternate Manufacturer: Texas Instruments; SizeAreaWB_mm2: 10.4675; SizeZ_mm: 0.87; SizeX_mm: 1.65; SizeY_mm: 2.95; SizeArea_mm2: 4.8675; CompType: IC; AEC Qualified: N; AEC Category: Q200
U4 = CMP-0080906-1: High-Accuracy, Fixed-Threshold OV/UV Monitor, DDC0006A (SOT-23-T-6); Alternate PartNumber: TPS3702CX12DDCR; Alternate Manufacturer: Texas Instruments; SizeAreaWB_mm2: 10.4675; SizeZ_mm: 0.87; SizeX_mm: 1.65; SizeY_mm: 2.95; SizeArea_mm2: 4.8675; CompType: IC; AEC Qualified: N; AEC Category: Q200
U5 = CMP-0065661-2: Low Jitter, 1:4 LVCMOS Fan-out Clock Buffer, PW0008A (TSSOP-8); Alternate Manufacturer: Texas Instruments; Green_Lifecycle: Active; SizeAreaWB_mm2: 42.0; Green_REACh: Passed; U/M: EA; SizeZ_mm: 1.2; SizeX_mm: 6.4; SizeY_mm: 3.0; SizeArea_mm2: 19.2; CompType: IC
Y1 = CMP-0082061-2: Oscillator, 25 MHz, 15 pF, SMD; Manufacturer: ECS Inc.; Frequency Stability: 10 ppm; SizeAreaWB_mm2: 10.5; SizeArea_mm2: 5; AEC Qualified: N; AEC Category: Q200; TaMax_C: 85°C; SizeZ_mm: 1; Frequency_Fixed: 25MHz; TaMin_C: -40°C; SizeY_mm: 2.5; Load Capacitance: 15 pF; SizeX_mm: 2
Y2 = CMP-0082062-2: Oscillator, 20 MHz, 15 pF, SMD; Manufacturer: ECS Inc.; Frequency Stability: 10 ppm; SizeAreaWB_mm2: 10.5; SizeArea_mm2: 5; AEC Qualified: N; AEC Category: Q200; TaMax_C: 85°C; SizeZ_mm: 1; Frequency_Fixed: 20MHz; TaMin_C: -40°C; SizeY_mm: 2.5; Load Capacitance: 15 pF; SizeX_mm: 2

## Sheet MCU063B_ADC.SchDoc
size 431 x 279 mm; Date: Not shown in title block; ApprovedBy: Not shown in title block; CheckedBy: Not shown in title block; Author: Not shown in title block; CompanyName: Not shown in title block; DrawnBy: Cody Watkins; Engineer: Not shown in title block; Organization: Not shown in title block; Address1: Not shown in title block; Address2: Not shown in title block; Address3: Not shown in title block; Address4: Not shown in title block; DocumentNumber: 4; Revision: Use project parameter SCH_Rev; SheetNumber: 4; SheetTotal: 11; PageSetup: Record=PageOptions¦CenterHorizontal=True¦CenterVertical=True¦PrintScale=1.00¦XCorrection=1.00¦YCorrection=1.00¦PrintKind=0¦BorderSize=5000000¦LeftOffset=0¦BottomOffset=0¦Orientation=2¦PaperLength=1000¦PaperWidth=1000¦Scale=100¦PaperSource=15¦PrintQuality=600¦MediaType=1¦DitherType=10¦PaperKind=Letter¦PrintScaleMode=1
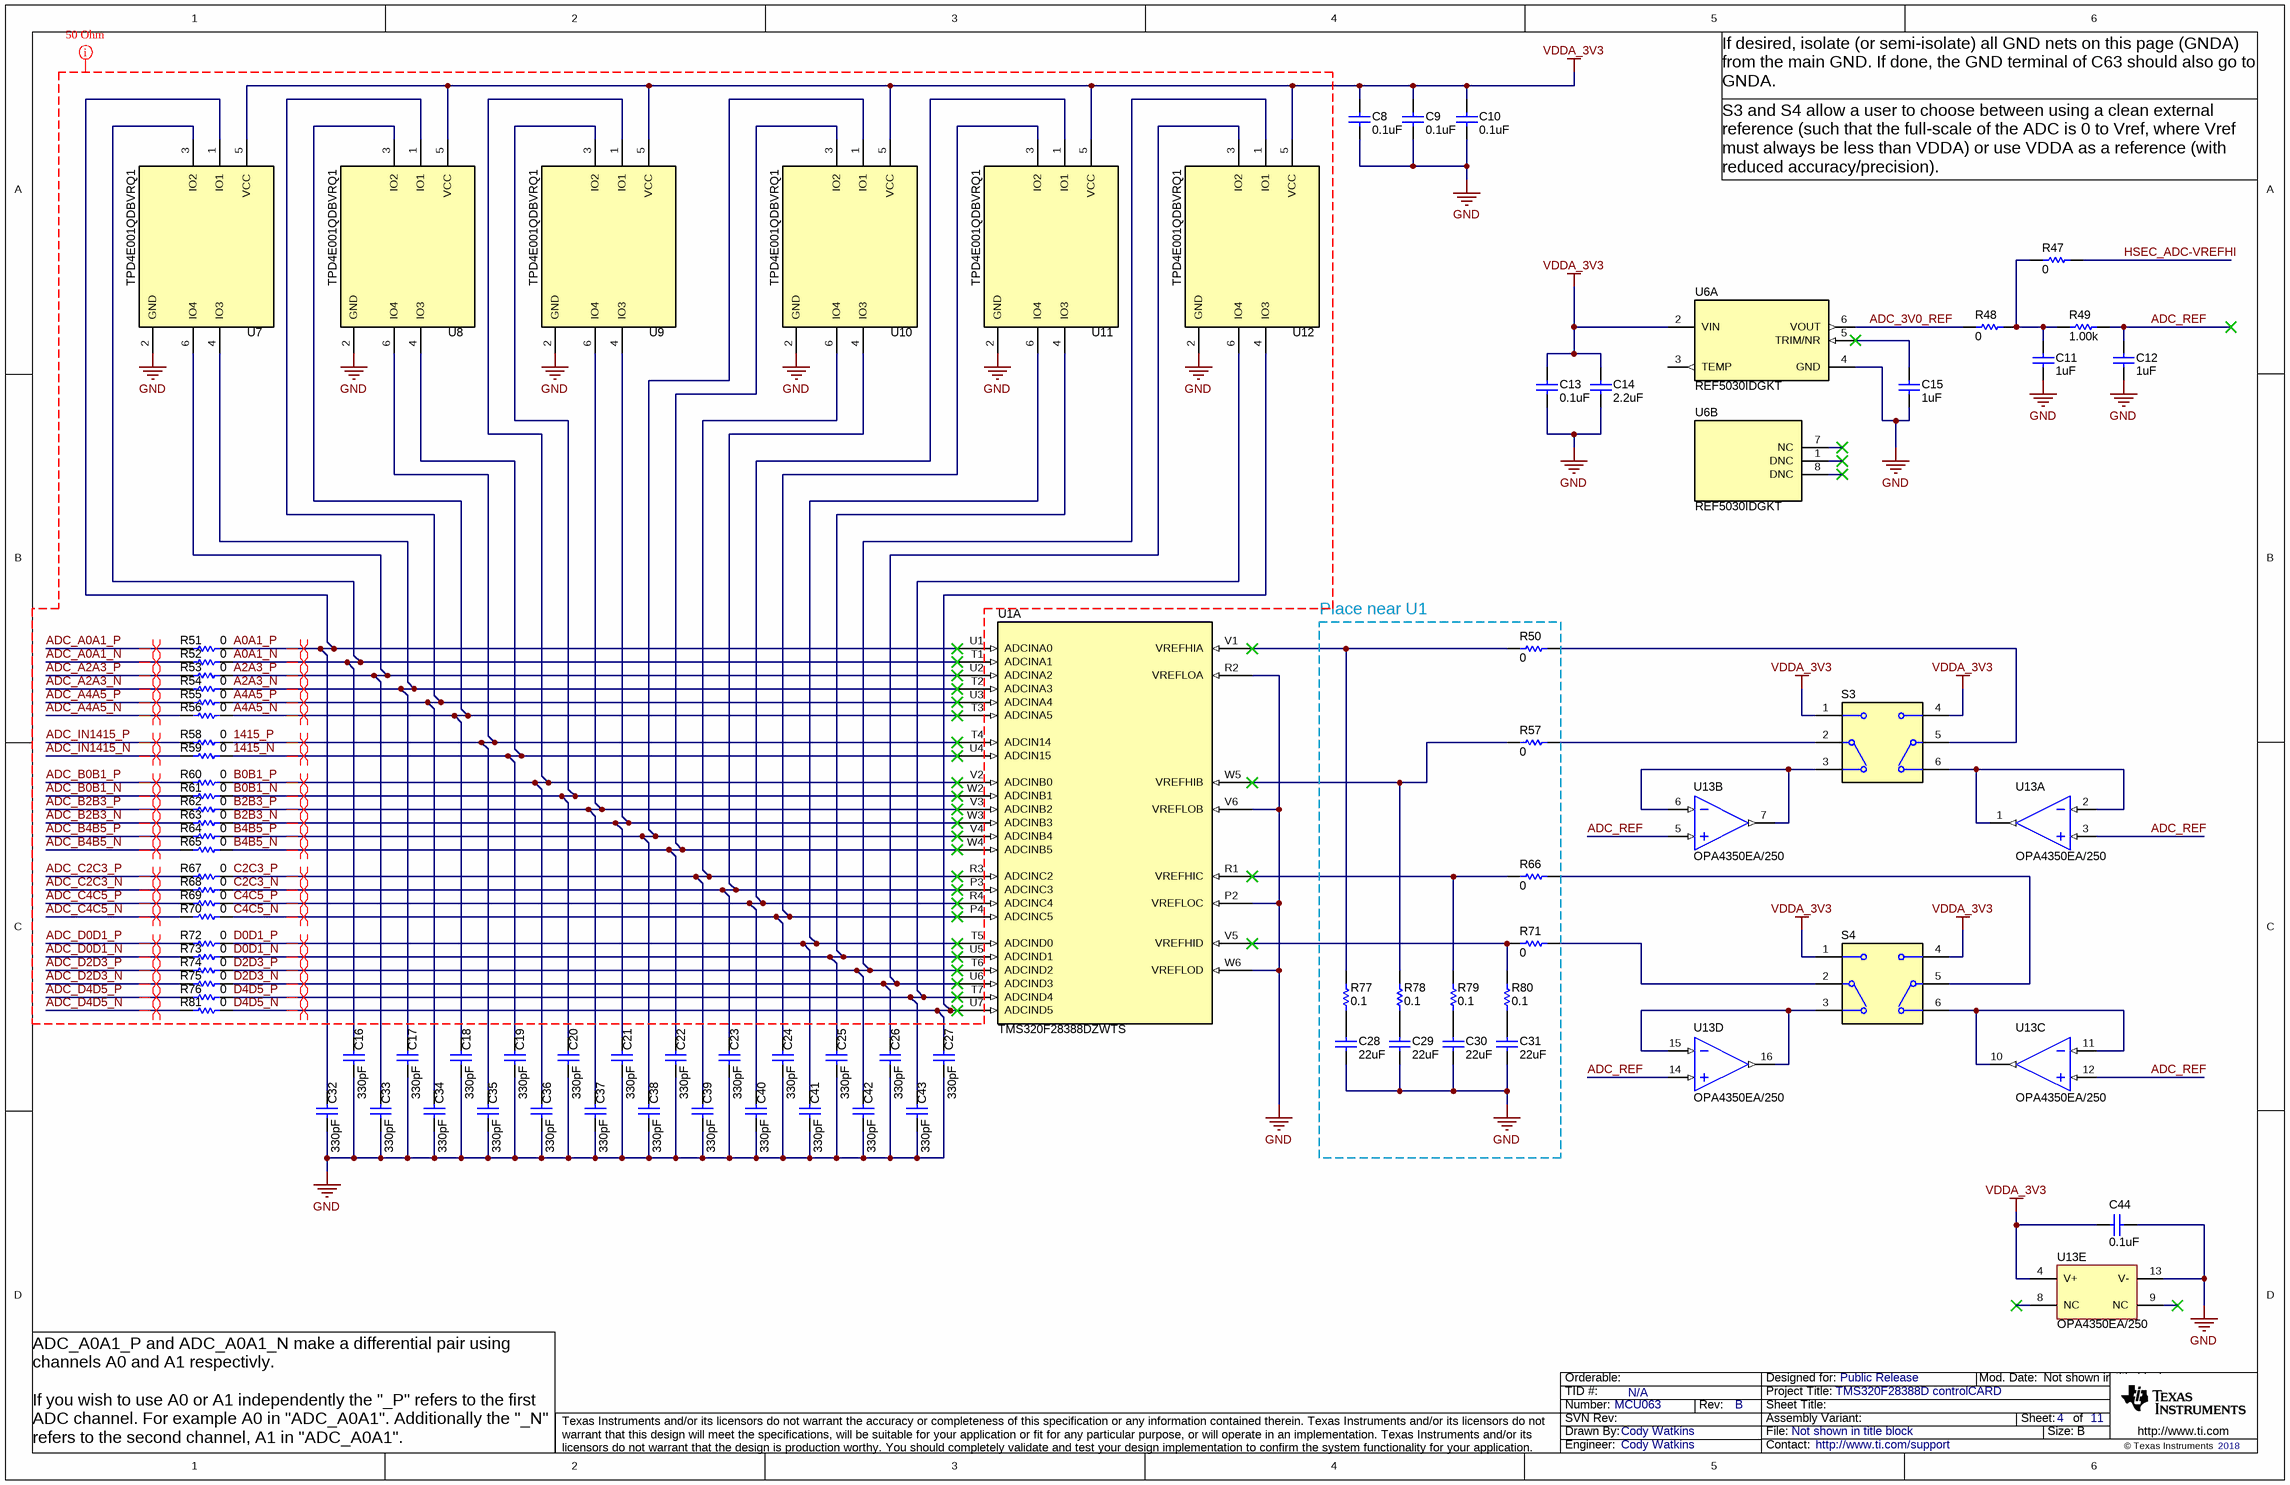
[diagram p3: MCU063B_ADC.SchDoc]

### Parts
C8  ValueDisplayed: 0.1uF  [0603]  (hidden comment: C0603C104K8RACTU)
C9  ValueDisplayed: 0.1uF  [0603]  (hidden comment: C0603C104K8RACTU)
C10  ValueDisplayed: 0.1uF  [0603]  (hidden comment: C0603C104K8RACTU)
C11  ValueDisplayed: 1uF  [0603]  (hidden comment: C0603C105Z9VACTU)
C12  ValueDisplayed: 1uF  [0603]  (hidden comment: C0603C105Z9VACTU)
C13  ValueDisplayed: 0.1uF  [0603]  (hidden comment: C0603C104K8RACTU)
C14  ValueDisplayed: 2.2uF  [0603]  (hidden comment: C0603C225K9PACTU)
C15  ValueDisplayed: 1uF  [0603]  (hidden comment: C0603C105Z9VACTU)
C16  ValueDisplayed: 330pF  [0603]  (hidden comment: C0603C331J5GACTU)
C17  ValueDisplayed: 330pF  [0603]  (hidden comment: C0603C331J5GACTU)
C18  ValueDisplayed: 330pF  [0603]  (hidden comment: C0603C331J5GACTU)
C19  ValueDisplayed: 330pF  [0603]  (hidden comment: C0603C331J5GACTU)
C20  ValueDisplayed: 330pF  [0603]  (hidden comment: C0603C331J5GACTU)
C21  ValueDisplayed: 330pF  [0603]  (hidden comment: C0603C331J5GACTU)
C22  ValueDisplayed: 330pF  [0603]  (hidden comment: C0603C331J5GACTU)
C23  ValueDisplayed: 330pF  [0603]  (hidden comment: C0603C331J5GACTU)
C24  ValueDisplayed: 330pF  [0603]  (hidden comment: C0603C331J5GACTU)
C25  ValueDisplayed: 330pF  [0603]  (hidden comment: C0603C331J5GACTU)
C26  ValueDisplayed: 330pF  [0603]  (hidden comment: C0603C331J5GACTU)
C27  ValueDisplayed: 330pF  [0603]  (hidden comment: C0603C331J5GACTU)
C28  ValueDisplayed: 22uF  [0603]  (hidden comment: GRM188R61A226ME15D)
C29  ValueDisplayed: 22uF  [0603]  (hidden comment: GRM188R61A226ME15D)
C30  ValueDisplayed: 22uF  [0603]  (hidden comment: GRM188R61A226ME15D)
C31  ValueDisplayed: 22uF  [0603]  (hidden comment: GRM188R61A226ME15D)
C32  ValueDisplayed: 330pF  [0603]  (hidden comment: C0603C331J5GACTU)
C33  ValueDisplayed: 330pF  [0603]  (hidden comment: C0603C331J5GACTU)
C34  ValueDisplayed: 330pF  [0603]  (hidden comment: C0603C331J5GACTU)
C35  ValueDisplayed: 330pF  [0603]  (hidden comment: C0603C331J5GACTU)
C36  ValueDisplayed: 330pF  [0603]  (hidden comment: C0603C331J5GACTU)
C37  ValueDisplayed: 330pF  [0603]  (hidden comment: C0603C331J5GACTU)
C38  ValueDisplayed: 330pF  [0603]  (hidden comment: C0603C331J5GACTU)
C39  ValueDisplayed: 330pF  [0603]  (hidden comment: C0603C331J5GACTU)
C40  ValueDisplayed: 330pF  [0603]  (hidden comment: C0603C331J5GACTU)
C41  ValueDisplayed: 330pF  [0603]  (hidden comment: C0603C331J5GACTU)
C42  ValueDisplayed: 330pF  [0603]  (hidden comment: C0603C331J5GACTU)
C43  ValueDisplayed: 330pF  [0603]  (hidden comment: C0603C331J5GACTU)
C44  ValueDisplayed: 0.1uF  [0603]  (hidden comment: C0603C104K8RACTU)
R47  ValueDisplayed: 0  [0603]  (hidden comment: CRCW06030000Z0EA)
R48  ValueDisplayed: 0  [0603]  (hidden comment: CRCW06030000Z0EA)
R49  ValueDisplayed: 1.00k  [0603]  (hidden comment: RC0603FR-071KL)
R50  ValueDisplayed: 0  [0603]  (hidden comment: CRCW06030000Z0EA)
R51  ValueDisplayed: 0  [0603]  (hidden comment: CRCW06030000Z0EA)
R52  ValueDisplayed: 0  [0603]  (hidden comment: CRCW06030000Z0EA)
R53  ValueDisplayed: 0  [0603]  (hidden comment: CRCW06030000Z0EA)
R54  ValueDisplayed: 0  [0603]  (hidden comment: CRCW06030000Z0EA)
R55  ValueDisplayed: 0  [0603]  (hidden comment: CRCW06030000Z0EA)
R56  ValueDisplayed: 0  [0603]  (hidden comment: CRCW06030000Z0EA)
R57  ValueDisplayed: 0  [0603]  (hidden comment: CRCW06030000Z0EA)
R58  ValueDisplayed: 0  [0603]  (hidden comment: CRCW06030000Z0EA)
R59  ValueDisplayed: 0  [0603]  (hidden comment: CRCW06030000Z0EA)
R60  ValueDisplayed: 0  [0603]  (hidden comment: CRCW06030000Z0EA)
R61  ValueDisplayed: 0  [0603]  (hidden comment: CRCW06030000Z0EA)
R62  ValueDisplayed: 0  [0603]  (hidden comment: CRCW06030000Z0EA)
R63  ValueDisplayed: 0  [0603]  (hidden comment: CRCW06030000Z0EA)
R64  ValueDisplayed: 0  [0603]  (hidden comment: CRCW06030000Z0EA)
R65  ValueDisplayed: 0  [0603]  (hidden comment: CRCW06030000Z0EA)
R66  ValueDisplayed: 0  [0603]  (hidden comment: CRCW06030000Z0EA)
R67  ValueDisplayed: 0  [0603]  (hidden comment: CRCW06030000Z0EA)
R68  ValueDisplayed: 0  [0603]  (hidden comment: CRCW06030000Z0EA)
R69  ValueDisplayed: 0  [0603]  (hidden comment: CRCW06030000Z0EA)
R70  ValueDisplayed: 0  [0603]  (hidden comment: CRCW06030000Z0EA)
R71  ValueDisplayed: 0  [0603]  (hidden comment: CRCW06030000Z0EA)
R72  ValueDisplayed: 0  [0603]  (hidden comment: CRCW06030000Z0EA)
R73  ValueDisplayed: 0  [0603]  (hidden comment: CRCW06030000Z0EA)
R74  ValueDisplayed: 0  [0603]  (hidden comment: CRCW06030000Z0EA)
R75  ValueDisplayed: 0  [0603]  (hidden comment: CRCW06030000Z0EA)
R76  ValueDisplayed: 0  [0603]  (hidden comment: CRCW06030000Z0EA)
R77  ValueDisplayed: 0.1  [0402]  (hidden comment: ERJ2BWFR100X)
R78  ValueDisplayed: 0.1  [0402]  (hidden comment: ERJ2BWFR100X)
R79  ValueDisplayed: 0.1  [0402]  (hidden comment: ERJ2BWFR100X)
R80  ValueDisplayed: 0.1  [0402]  (hidden comment: ERJ2BWFR100X)
R81  ValueDisplayed: 0  [0603]  (hidden comment: CRCW06030000Z0EA)
S3  CAS-D20TA  [SW_CAS-D20TA]  (value not drawn)
S4  CAS-D20TA  [SW_CAS-D20TA]  (value not drawn)
U1  TMS320F28388DZWTS  [ZWT0337A]  (part A of 5)
U6  REF5030IDGKT  [DGK0008A_N]  (parts A,B of 2)
U7  TPD4E001QDBVRQ1  [DBV0006A_N]
U8  TPD4E001QDBVRQ1  [DBV0006A_N]
U9  TPD4E001QDBVRQ1  [DBV0006A_N]
U10  TPD4E001QDBVRQ1  [DBV0006A_N]
U11  TPD4E001QDBVRQ1  [DBV0006A_N]
U12  TPD4E001QDBVRQ1  [DBV0006A_N]
U13  OPA4350EA/250  [DBQ0016A_N]  (parts A,B,C,D,E of 5)

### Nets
GND: C8.2 C9.2 C10.2 C11.2 C12.2 C13.2 C14.2 C15.2 C16.2 C17.2 C18.2 C19.2 C20.2 C21.2 C22.2 C23.2 C24.2 C25.2 C26.2 C27.2 C28.2 C29.2 C30.2 C31.2 C32.2 C33.2 C34.2 C35.2 C36.2 C37.2 C38.2 C39.2 C40.2 C41.2 C42.2 C43.2 C44.1 U1.P2(VREFLOC) U1.R2(VREFLOA) U1.V6(VREFLOB) U1.W6(VREFLOD) U6.4(GND) U7.2(GND) U8.2(GND) U9.2(GND) U10.2(GND) U11.2(GND) U12.2(GND) U13.13(V-)
VDDA_3V3: C8.1 C9.1 C10.1 C13.1 C14.1 C44.2 S3.1 S3.4 S4.1 S4.4 U6.2(VIN) U7.5(VCC) U8.5(VCC) U9.5(VCC) U10.5(VCC) U11.5(VCC) U12.5(VCC) U13.4(V+)
1415_N: C19.1 R59.1 U1.U4(ADCIN15) U8.4(IO3)
1415_P: C35.1 R58.1 U1.T4(ADCIN14) U8.6(IO4)
A0A1_N: C16.1 R52.1 U1.T1(ADCINA1) U7.3(IO2)
A0A1_P: C32.1 R51.1 U1.U1(ADCINA0) U7.1(IO1)
A2A3_N: C17.1 R54.1 U1.T2(ADCINA3) U7.4(IO3)
A2A3_P: C33.1 R53.1 U1.U2(ADCINA2) U7.6(IO4)
A4A5_N: C18.1 R56.1 U1.T3(ADCINA5) U8.3(IO2)
A4A5_P: C34.1 R55.1 U1.U3(ADCINA4) U8.1(IO1)
ADC_3V0_REF: R48.2 U6.6(VOUT)
ADC_A0A1_N: R52.2
ADC_A0A1_P: R51.2
ADC_A2A3_N: R54.2
ADC_A2A3_P: R53.2
ADC_A4A5_N: R56.2
ADC_A4A5_P: R55.2
ADC_B0B1_N: R61.2
ADC_B0B1_P: R60.2
ADC_B2B3_N: R63.2
ADC_B2B3_P: R62.2
ADC_B4B5_N: R65.2
ADC_B4B5_P: R64.2
ADC_C2C3_N: R68.2
ADC_C2C3_P: R67.2
ADC_C4C5_N: R70.2
ADC_C4C5_P: R69.2
ADC_D0D1_N: R73.2
ADC_D0D1_P: R72.2
ADC_D2D3_N: R75.2
ADC_D2D3_P: R74.2
ADC_D4D5_N: R81.2
ADC_D4D5_P: R76.2
ADC_IN1415_N: R59.2
ADC_IN1415_P: R58.2
ADC_REF: C12.1 R49.2 U13.3(IN_A+) U13.5(IN_B+) U13.12(IN_C+) U13.14(IN_D+)
B0B1_N: C20.1 R61.1 U1.W2(ADCINB1) U9.3(IO2)
B0B1_P: C36.1 R60.1 U1.V2(ADCINB0) U9.1(IO1)
B2B3_N: C21.1 R63.1 U1.W3(ADCINB3) U9.4(IO3)
B2B3_P: C37.1 R62.1 U1.V3(ADCINB2) U9.6(IO4)
B4B5_N: C22.1 R65.1 U1.W4(ADCINB5) U10.3(IO2)
B4B5_P: C38.1 R64.1 U1.V4(ADCINB4) U10.1(IO1)
C2C3_N: C23.1 R68.1 U1.P3(ADCINC3) U10.4(IO3)
C2C3_P: C39.1 R67.1 U1.R3(ADCINC2) U10.6(IO4)
C4C5_N: C24.1 R70.1 U1.P4(ADCINC5) U11.3(IO2)
C4C5_P: C40.1 R69.1 U1.R4(ADCINC4) U11.1(IO1)
D0D1_N: C25.1 R73.1 U1.U5(ADCIND1) U11.4(IO3)
D0D1_P: C41.1 R72.1 U1.T5(ADCIND0) U11.6(IO4)
D2D3_N: C26.1 R75.1 U1.U6(ADCIND3) U12.3(IO2)
D2D3_P: C42.1 R74.1 U1.T6(ADCIND2) U12.1(IO1)
D4D5_N: C27.1 R81.1 U1.U7(ADCIND5) U12.4(IO3)
D4D5_P: C43.1 R76.1 U1.T7(ADCIND4) U12.6(IO4)
HSEC_ADC-VREFHI: R47.1
NetC11_1: C11.1 R47.2 R48.1 R49.1
NetC15_1: C15.1 U6.5(TRIM/NR)
NetC28_1: C28.1 R77.2
NetC29_1: C29.1 R78.2
NetC30_1: C30.1 R79.2
NetC31_1: C31.1 R80.2
NetR50_1: R50.1 S3.5(C)
NetR50_2: R50.2 R77.1 U1.V1(VREFHIA)
NetR57_1: R57.1 S3.2(C)
NetR57_2: R57.2 R78.1 U1.W5(VREFHIB)
NetR66_1: R66.1 S4.5(C)
NetR66_2: R66.2 R79.1 U1.R1(VREFHIC)
NetR71_1: R71.1 S4.2(C)
NetR71_2: R71.2 R80.1 U1.V5(VREFHID)
NetS3_3: S3.3 U13.6(IN_B-) U13.7(OUT_B)
NetS3_6: S3.6 U13.1(OUT_A) U13.2(IN_A-)
NetS4_3: S4.3 U13.15(IN_D-) U13.16(OUT_D)
NetS4_6: S4.6 U13.10(OUT_C) U13.11(IN_C-)

Not connected (* = marked no-connect by the designer): U6 1(DNC)* 3(TEMP) 7(NC)* 8(DNC)*; U13 8(NC)* 9(NC)*

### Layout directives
differential pair: 1415_N, 1415_P, A0A1_N, A0A1_P, A2A3_N, A2A3_P, A4A5_N, A4A5_P, ADC_A0A1_N, ADC_A0A1_P, ADC_A2A3_N, ADC_A2A3_P, ADC_A4A5_N, ADC_A4A5_P, ADC_B0B1_N, ADC_B0B1_P, ADC_B2B3_N, ADC_B2B3_P, ADC_B4B5_N, ADC_B4B5_P, ADC_C2C3_N, ADC_C2C3_P, ADC_C4C5_N, ADC_C4C5_P, ADC_D0D1_N, ADC_D0D1_P, ADC_D2D3_N, ADC_D2D3_P, ADC_D4D5_N, ADC_D4D5_P, ADC_IN1415_N, ADC_IN1415_P, B0B1_N, B0B1_P, B2B3_N, B2B3_P, B4B5_N, B4B5_P, C2C3_N, C2C3_P, C4C5_N, C4C5_P, D0D1_N, D0D1_P, D2D3_N, D2D3_P, D4D5_N, D4D5_P
50 Ohm Impedance: Undefined: 1415_N, 1415_P, A0A1_N, A0A1_P, A2A3_N, A2A3_P, A4A5_N, A4A5_P, ADC_A0A1_N, ADC_A0A1_P, ADC_A2A3_N, ADC_A2A3_P, ADC_A4A5_N, ADC_A4A5_P, ADC_B0B1_N, ADC_B0B1_P, ADC_B2B3_N, ADC_B2B3_P, ADC_B4B5_N, ADC_B4B5_P, ADC_C2C3_N, ADC_C2C3_P, ADC_C4C5_N, ADC_C4C5_P, ADC_D0D1_N, ADC_D0D1_P, ADC_D2D3_N, ADC_D2D3_P, ADC_D4D5_N, ADC_D4D5_P, ADC_IN1415_N, ADC_IN1415_P, B0B1_N, B0B1_P, B2B3_N, B2B3_P, B4B5_N, B4B5_P, C2C3_N, C2C3_P, C4C5_N, C4C5_P, D0D1_N, D0D1_P, D2D3_N, D2D3_P, D4D5_N, D4D5_P, GND

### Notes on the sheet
- If desired, isolate (or semi-isolate) all GND nets on this page (GNDA) from the main GND. If done, the GND terminal of C63 should also go to GNDA.
- S3 and S4 allow a user to choose between using a clean external reference (such that the full-scale of the ADC is 0 to Vref, where Vref must always be less than VDDA) or use VDDA as a reference (with reduced accuracy/precision).
- Place near U1
- ADC_A0A1_P and ADC_A0A1_N make a differential pair using channels A0 and A1 respectivly.
  If you wish to use A0 or A1 independently the "_P" refers to the first ADC channel. For example A0 in "ADC_A0A1". Additionally the "_N" refers to the second channel, A1 in "ADC_A0A1".

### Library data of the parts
C8-C10 C13 C44 = CMP-0006862-5: CAP, CERM, 0.1 uF, 10 V, +/- 10%, X7R, 0603; Manufacturer: Kemet; TaMin_C: -55°C; Polarized: N; SizeAreaWB_mm2: 4.68; Value1: Unknown; U/M: EA; Value: 0.1uF; TaMax_C: 125°C; SizeZ_mm: 1; SizeX_mm: 1.6; SizeY_mm: 0.8; Value2: 10V; SizeArea_mm2: 1.28; Cap_F: 100nF; AEC Category: Q200
C11 C12 C15 = CMP-0006871-4: CAP, CERM, 1 uF, 6.3 V, +80/-20%, Y5V, 0603; Manufacturer: Kemet; TaMin_C: -30°C; Polarized: N; SizeAreaWB_mm2: 4.68; Value1: Unknown; U/M: EA; Value: 1uF; TaMax_C: 85°C; Tolerance_%: 80%; SizeZ_mm: 1; SizeX_mm: 1.6; SizeY_mm: 0.8; Value2: 6.3V; SizeArea_mm2: 1.28; Cap_F: 1µF; AEC Category: Q200
C14 = CMP-0006907-5: CAP, CERM, 2.2 uF, 6.3 V, +/- 10%, X5R, 0603; Manufacturer: Kemet; TaMin_C: -55°C; Polarized: N; SizeAreaWB_mm2: 4.68; Value1: Unknown; U/M: EA; Value: 2.2uF; TaMax_C: 85°C; SizeZ_mm: 1; SizeX_mm: 1.6; SizeY_mm: 0.8; Value2: 6.3V; SizeArea_mm2: 1.28; Cap_F: 2.2µF; AEC Category: Q200
C16-C27 C32-C43 = CMP-0006920-4: CAP, CERM, 330 pF, 50 V, +/- 5%, C0G/NP0, 0603; Manufacturer: Kemet; TaMin_C: -55°C; Polarized: N; SizeAreaWB_mm2: 4.68; Value1: Unknown; U/M: EA; Value: 330pF; TaMax_C: 125°C; SizeZ_mm: 1; SizeX_mm: 1.6; SizeY_mm: 0.8; Value2: 50V; SizeArea_mm2: 1.28; AEC Category: Q200
C28-C31 = CMP-0007324-5: CAP, CERM, 22 uF, 10 V, +/- 20%, X5R, 0603; Manufacturer: MuRata; TaMin_C: -55°C; Polarized: N; SizeAreaWB_mm2: 4.68; Value1: Unknown; U/M: EA; Value: 22uF; TaMax_C: 85°C; SizeZ_mm: 1; SizeX_mm: 1.6; SizeY_mm: 0.8; Value2: 10V; SizeArea_mm2: 1.28; Cap_F: 22µF; AEC Category: Q200
R47 R48 R50-R76 R81 = CMP-0025697-4: as R21 on sheet MCU063B_Support
R49 = CMP-0022895-5: RES, 1.00 k, 1%, 0.1 W, 0603; Manufacturer: Yageo; Power_W: 100mW; TempCo: 100 ppm/C; Value_Code: 1k00; Value: 1.00k; EIA_Code: E96; Res_ohm: 1k; SizeX_mm: 1.6; SizeY_mm: 0.8; SizeZ_mm: 1; Value2: 0.1W; SizeArea_mm2: 1.28; AEC Qualified: N; VDC_V: 75V; AEC Category: Q200; SizeAreaWB_mm2: 4.68
R77-R80 = CMP-0078660-1: RES, 0.1, 1%, 0.25 W, 0402; Manufacturer: Panasonic; Power_W: 250mW; TempCo: 300 ppm/C; Value_Code: R100; Value: 0.1; EIA_Code: E96; Res_ohm: 1d; SizeX_mm: 1; SizeY_mm: 0.5; SizeZ_mm: 0.6; Value2: 0.25W; AEC Qualified: N; AEC Category: Q200
S3 S4 = CMP-0002233-1: Switch, Dual SPDT,  2 Pos, 0.1A, 6VDC, SMD; Manufacturer: Copal Electronics; CurrentRating_mA: 100A; SwitchFunction: On-On; VDC_V: 6V; PositionCount: 2
U1 = CMP-0081777-3: as U1 on sheet MCU063B_GPIO
U6 = CMP-0032596-2: Low Noise, Very Low Drift, Precision Series Voltage Reference, DGK0008A (VSSOP-8); Manufacturer: Texas Instruments; Temp Coeff(Max)(ppm/ degree C): 3; Iout/Iz(Max)(mA): 10; VI(Min)(V): 3.2; Eco-Plan: Green (RoHS & no Sb/Br); Initial Accuracy @ 25/deg C(%): 0.05; Iq(Max)(uA): 1000; VI(Max)(V): 18; Rating: Catalog; AEC Category: Q200; AEC Qualified: N; CompType: IC; SizeAreaWB_mm2: 23.6; SizeArea_mm2: 14.7; SizeX_mm: 4.9; SizeZ_mm: 1.1
U7-U12 = CMP-0066599-1: Automotive Low-Capacitance 4-Channel +/-15-kV ESD Protection Array for High-Speed Data Interfaces, DBV0006A (SOT-23-6); Alternate Manufacturer: Texas Instruments; SizeAreaWB_mm2: 14.82; U/M: EA; SizeZ_mm: 1.45; SizeX_mm: 2.8; SizeY_mm: 2.9; SizeArea_mm2: 8.12; CompType: IC
U13 = CMP-0041147-1: High-Speed, Single-Supply, Rail-to-Rail Operational Amplifier MicroAmplifier(TM) Series, 2.7 to 5.5 V, -55 to 150 degC, 16-pin SOP (DBQ16), Green (RoHS & no Sb/Br); Manufacturer: Texas Instruments; Number of Channels: 4; Vio (25C)(Max)(mV): 0.5; Total Supply Voltage(Min)(+5V is 5, +/-5V is 10): 2.7; Slew Rate(Typ)(V/us): 22; Total Supply Voltage(Max)(+5V is 5, +/-5V is 10): 5.5; Iq per channel(Max)(mA): 7.5; Vn at 1kHz(Typ)(nV/rtHz): 18; Sub Family: Low Input Bias Current Amp (<=10pA), Low Offset Voltage Amplifier (<=500uV), Low Supply Voltage Amplifier (<=2.7V), Precision Amplifier; IIB(Max)(pA): 10; CMRR(Min)(dB): 66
